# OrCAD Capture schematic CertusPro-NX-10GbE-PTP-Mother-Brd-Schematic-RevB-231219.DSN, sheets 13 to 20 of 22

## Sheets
13 12_FPGA_B5-2-1G_SFPS: size A3; title: 12_FPGA_B5-2-1G_SFPS
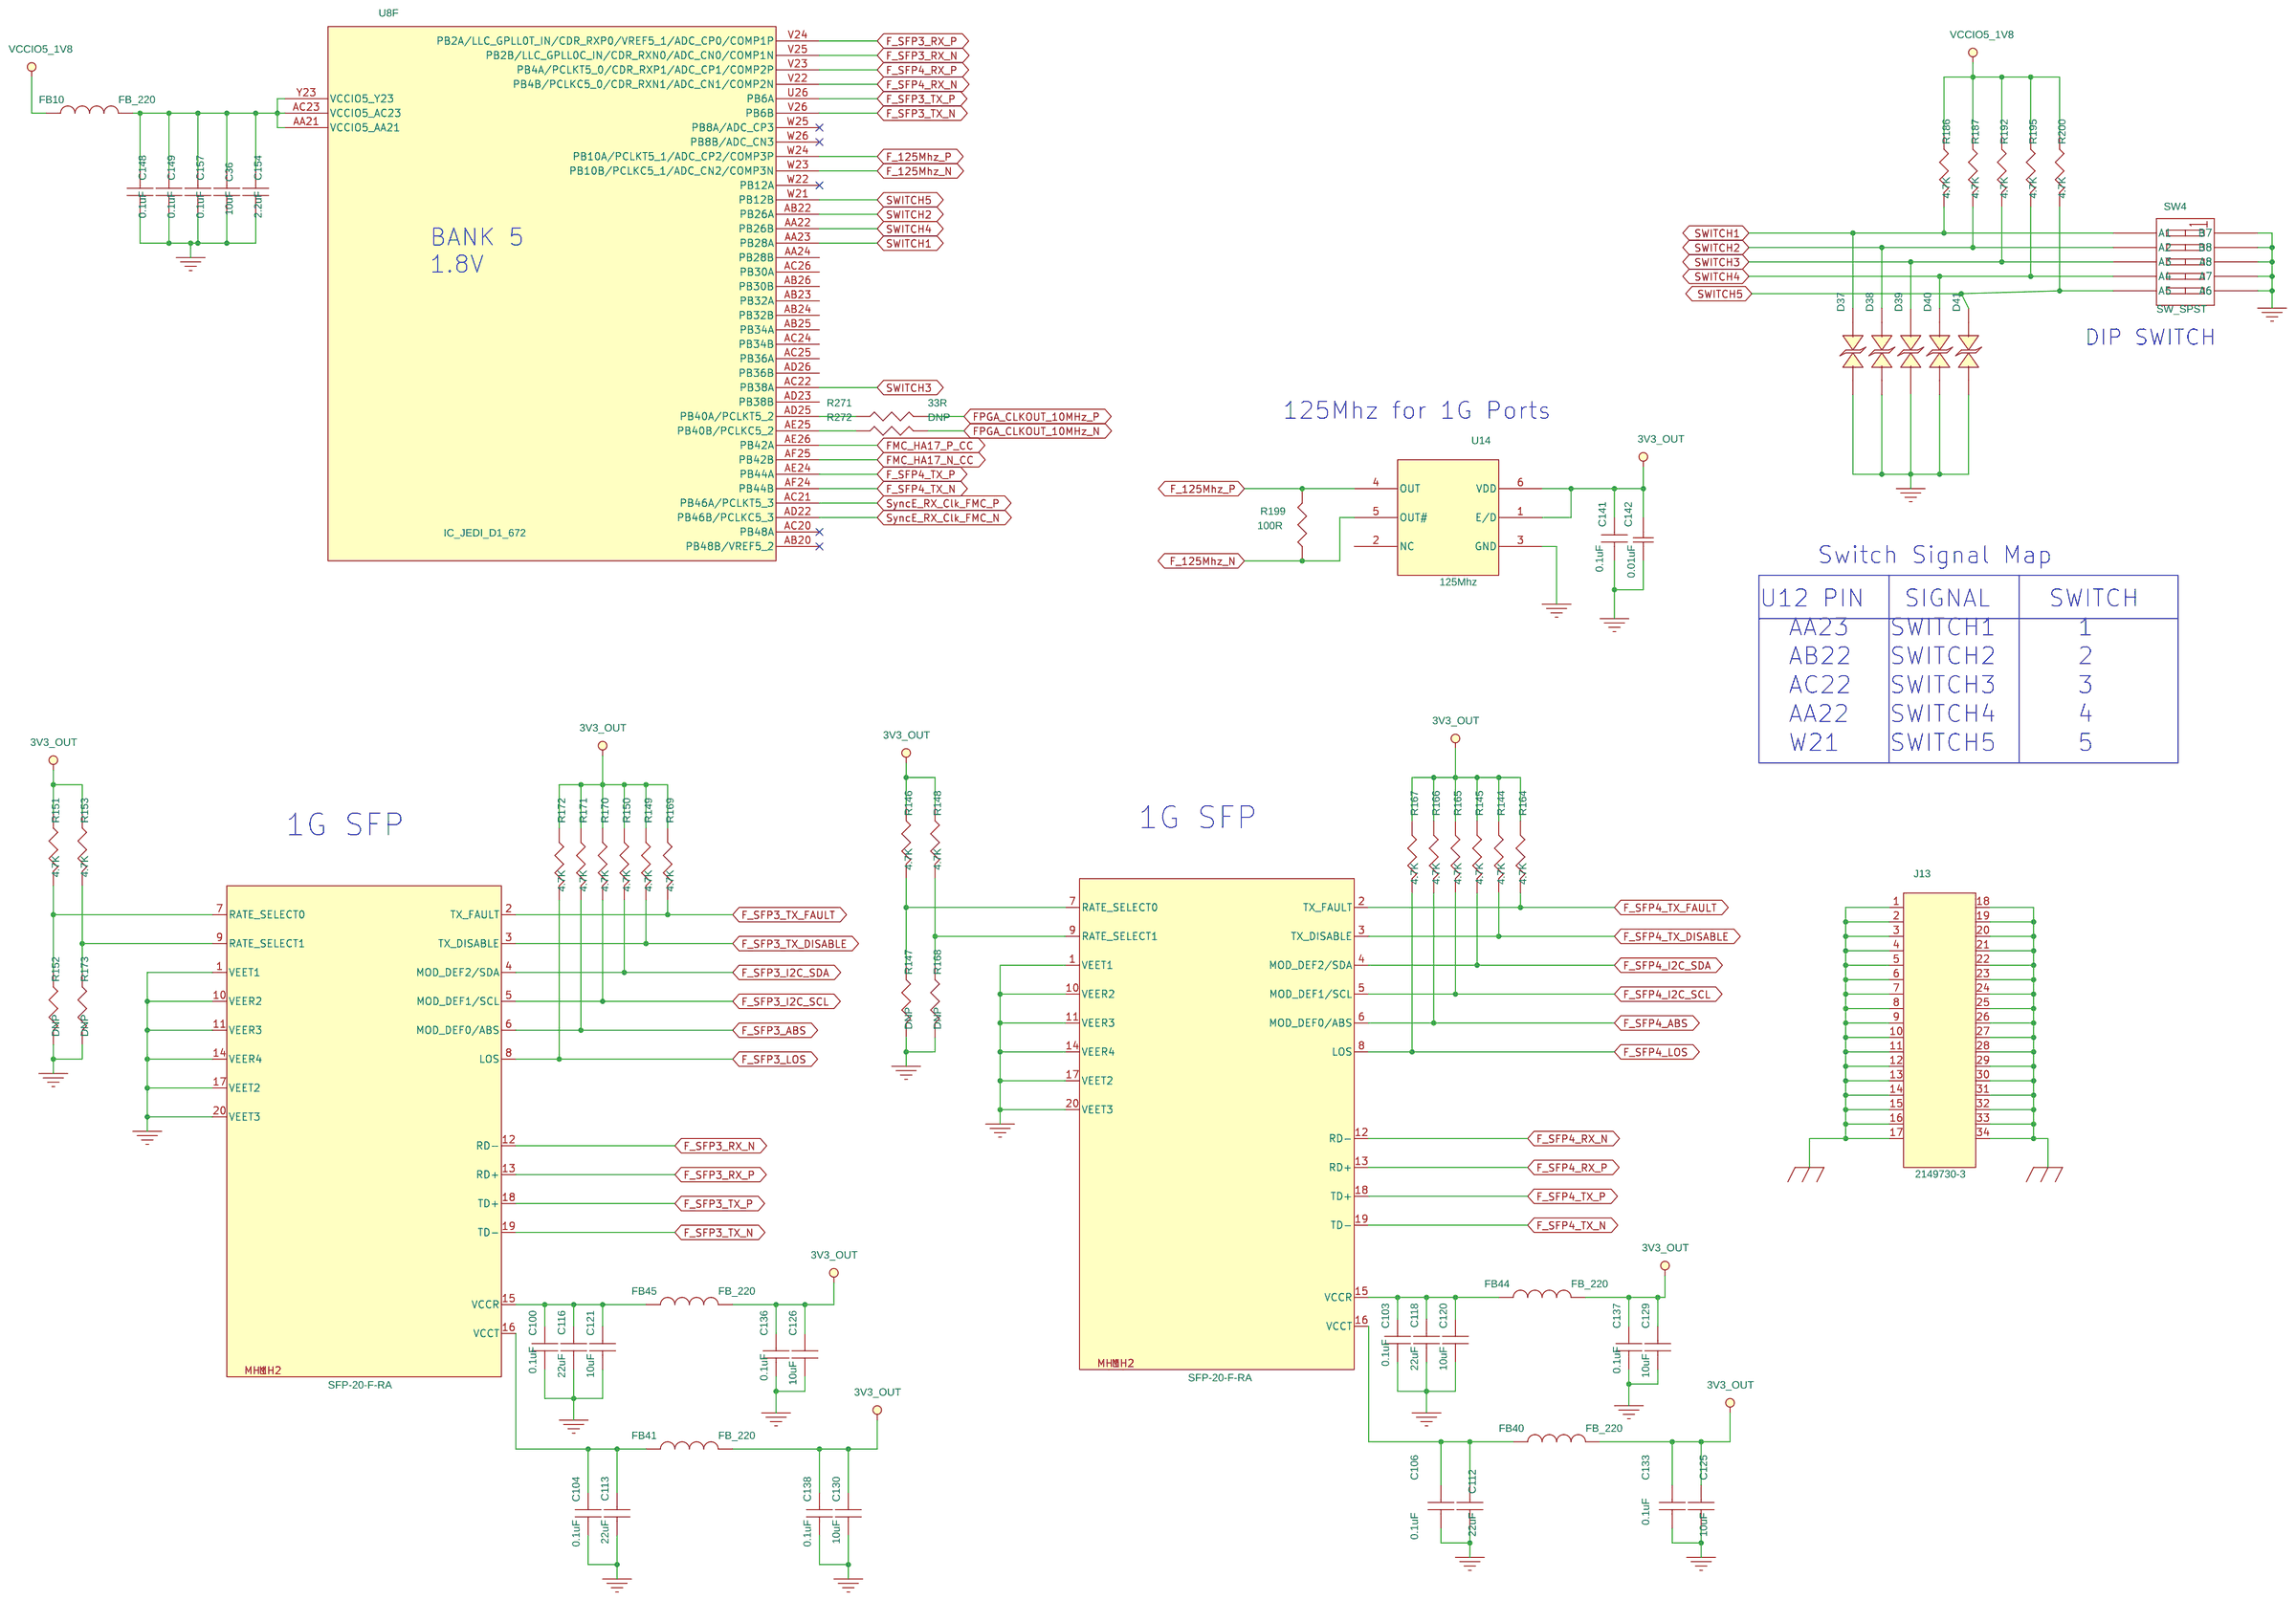
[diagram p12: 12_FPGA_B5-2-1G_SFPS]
14 10_FPGA_B2: size A3; title: 10_FPGA_B2-WR_Header
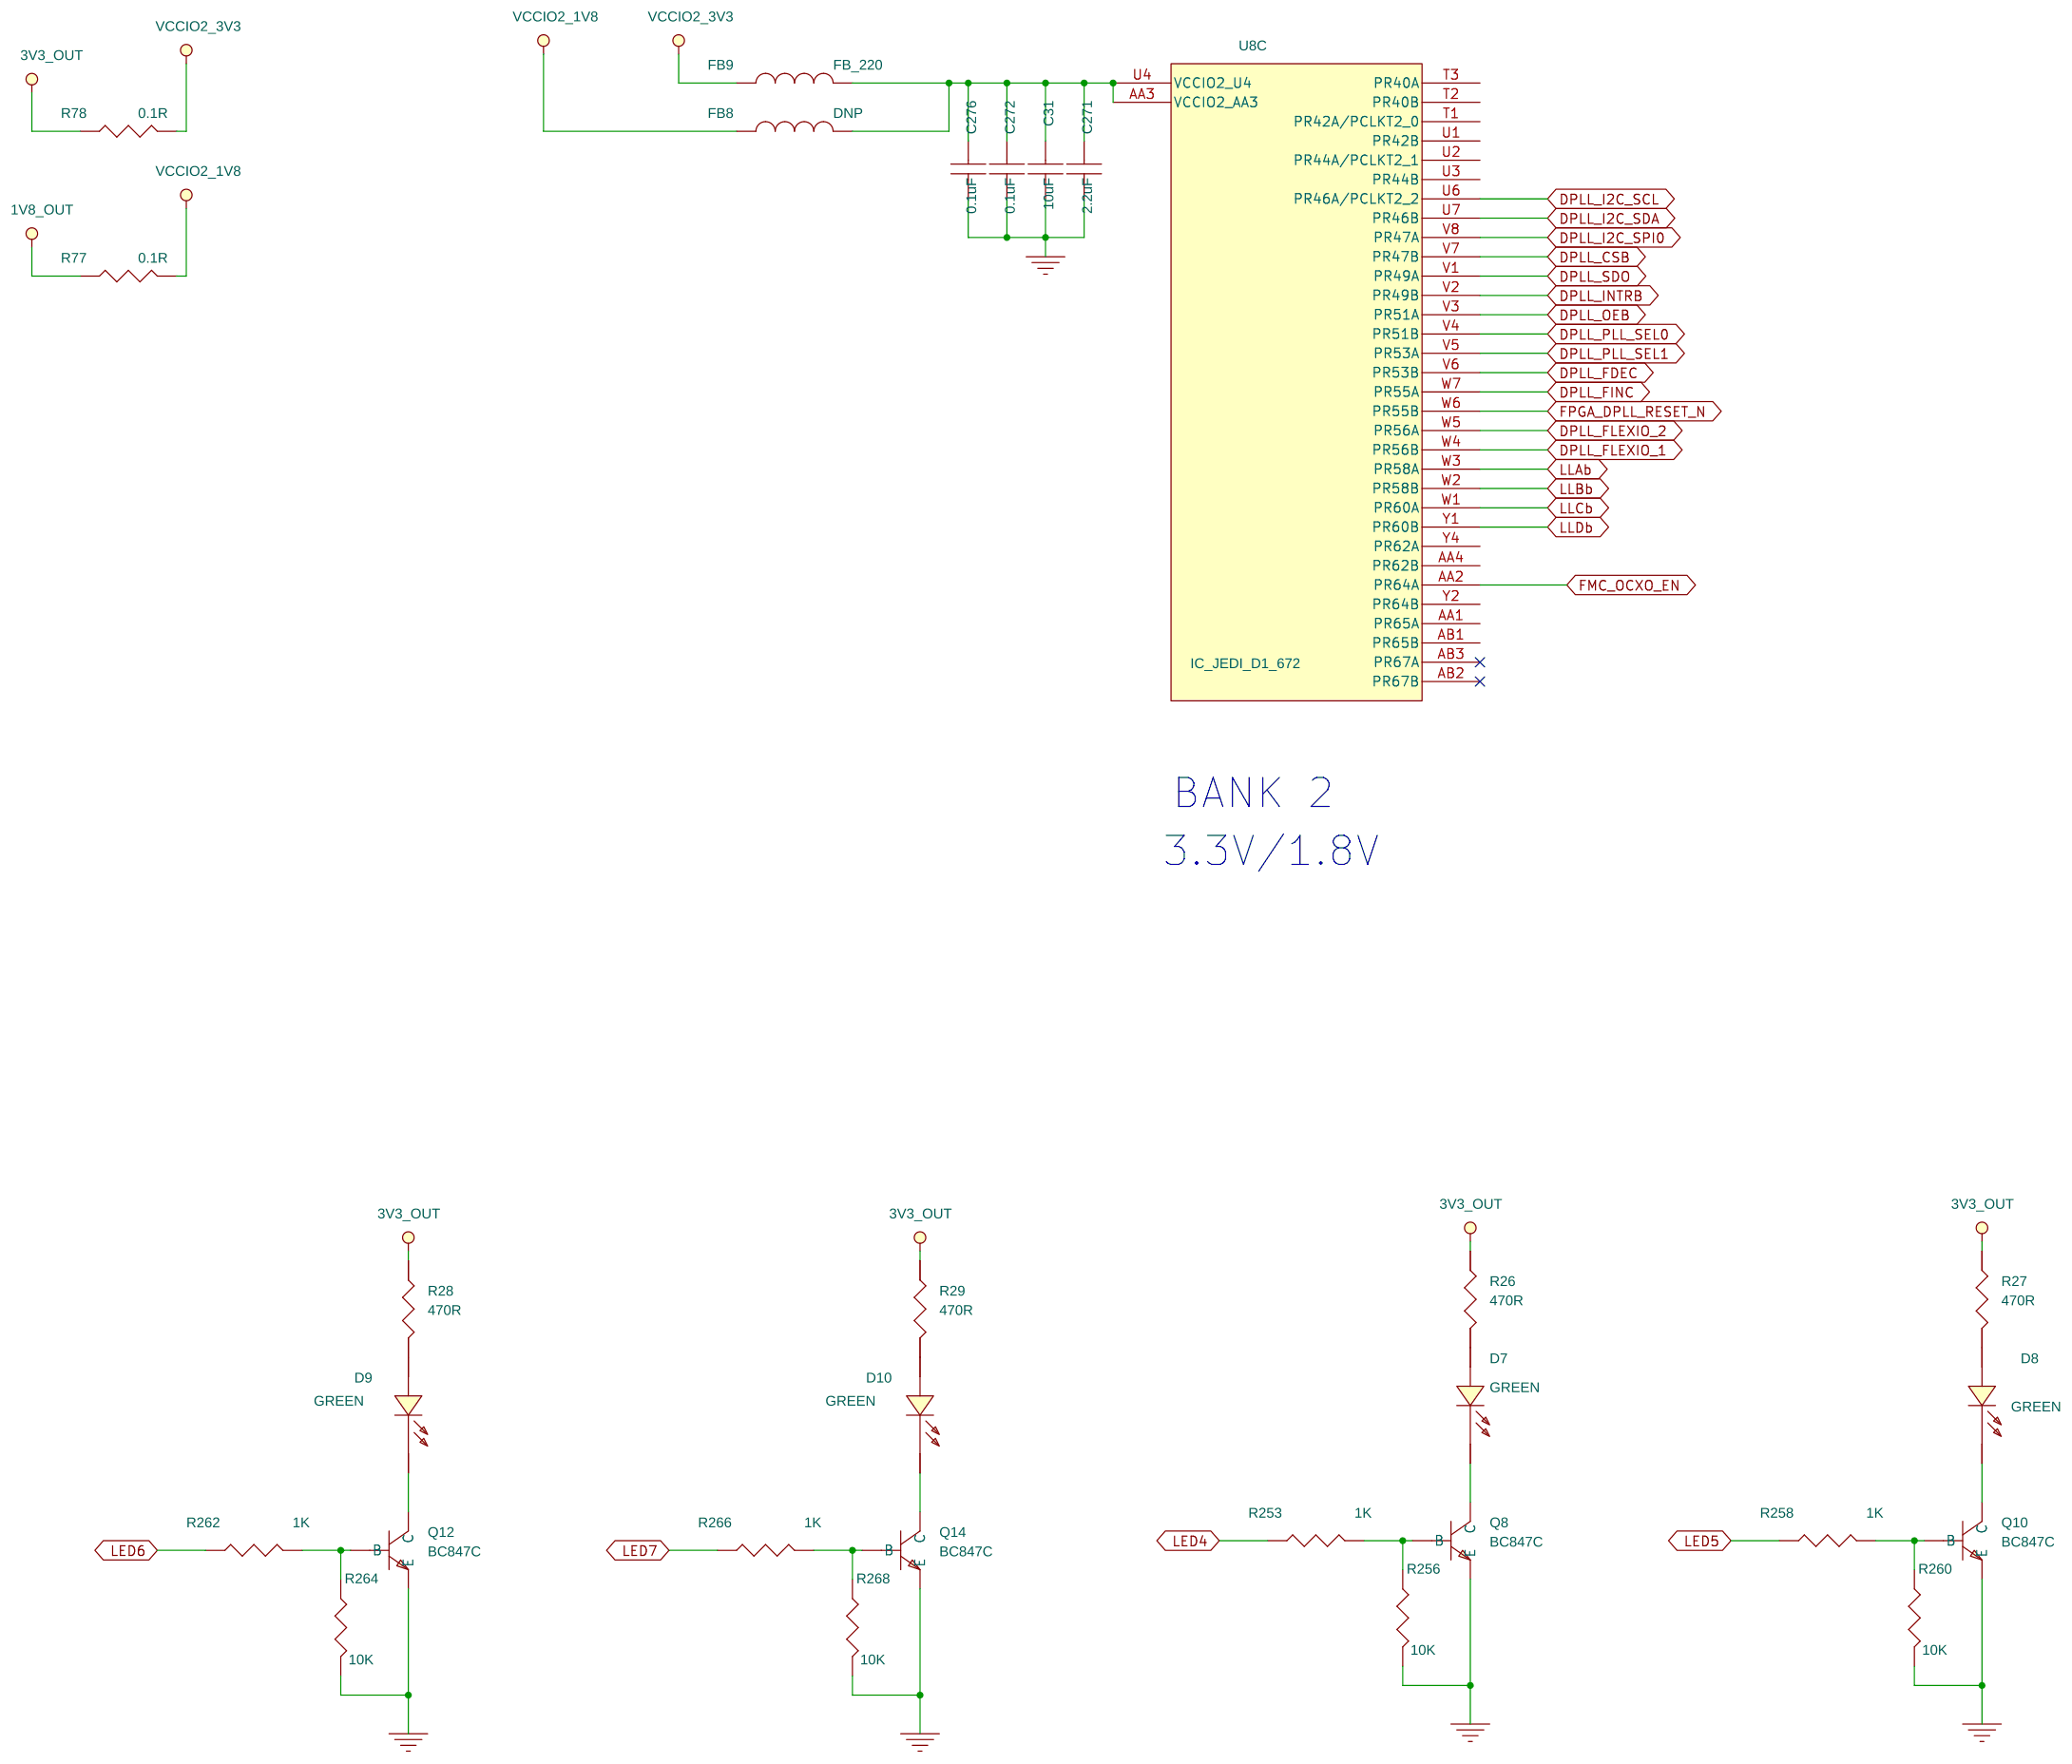
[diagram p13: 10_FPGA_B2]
15 15_FPGA_ADC: size A3; title: 15_FPGA_ADC
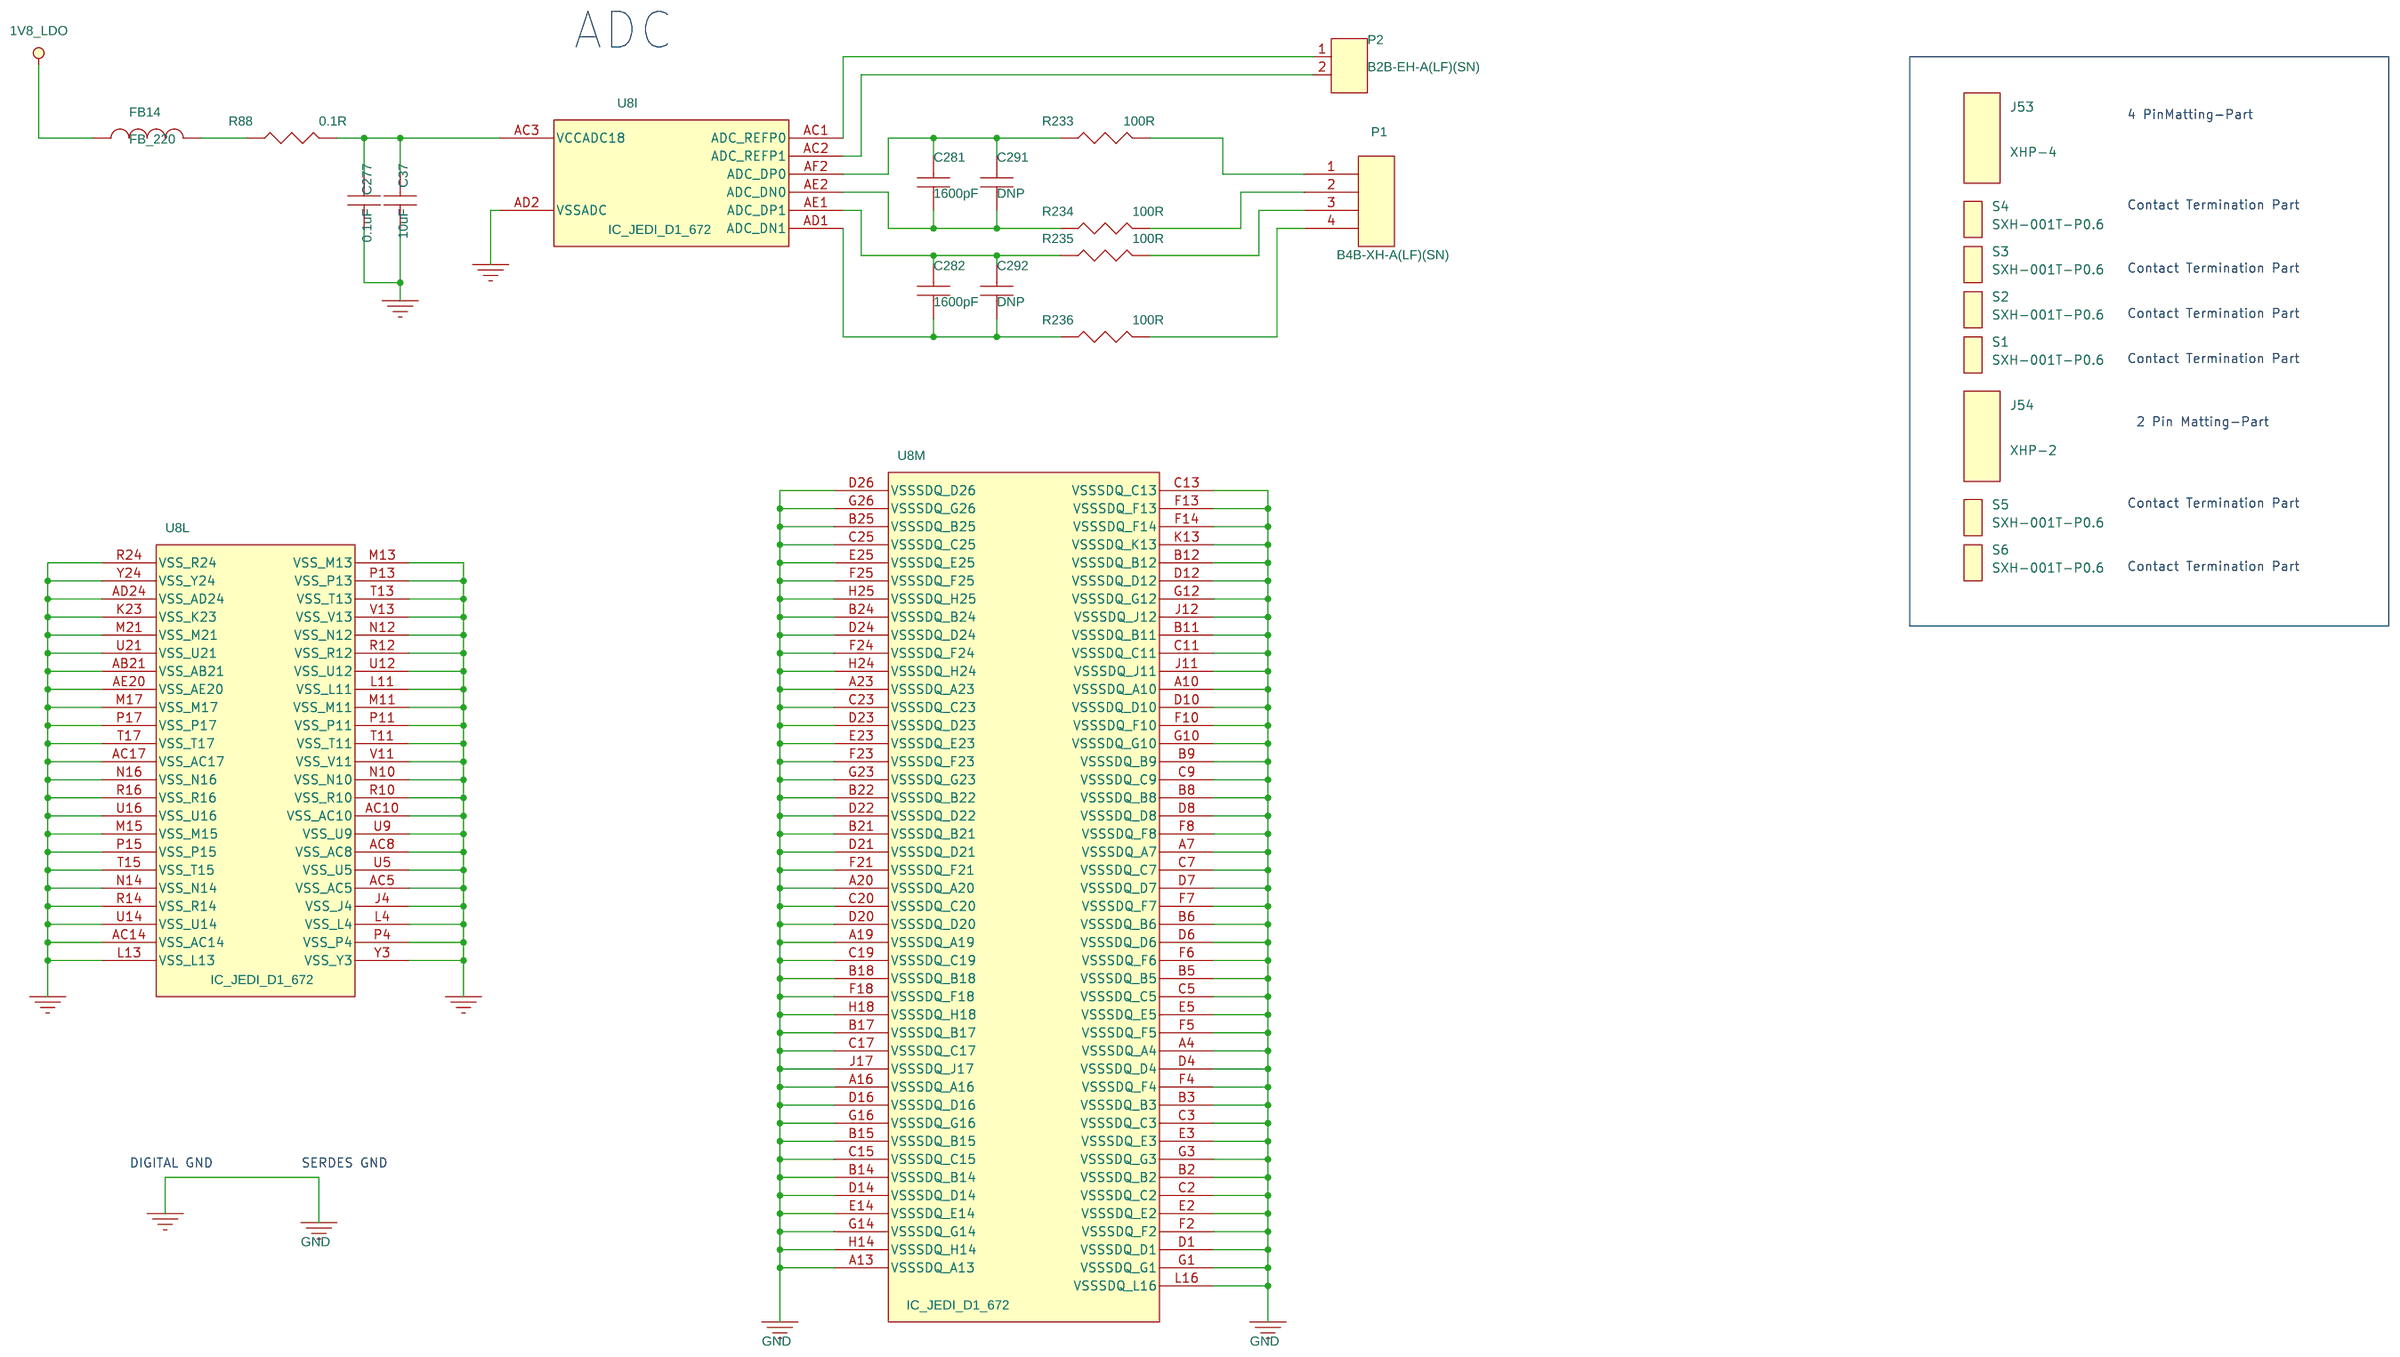
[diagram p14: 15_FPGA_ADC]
16 16_FTDI_USB: size A3; title: 16_FTDI_USB
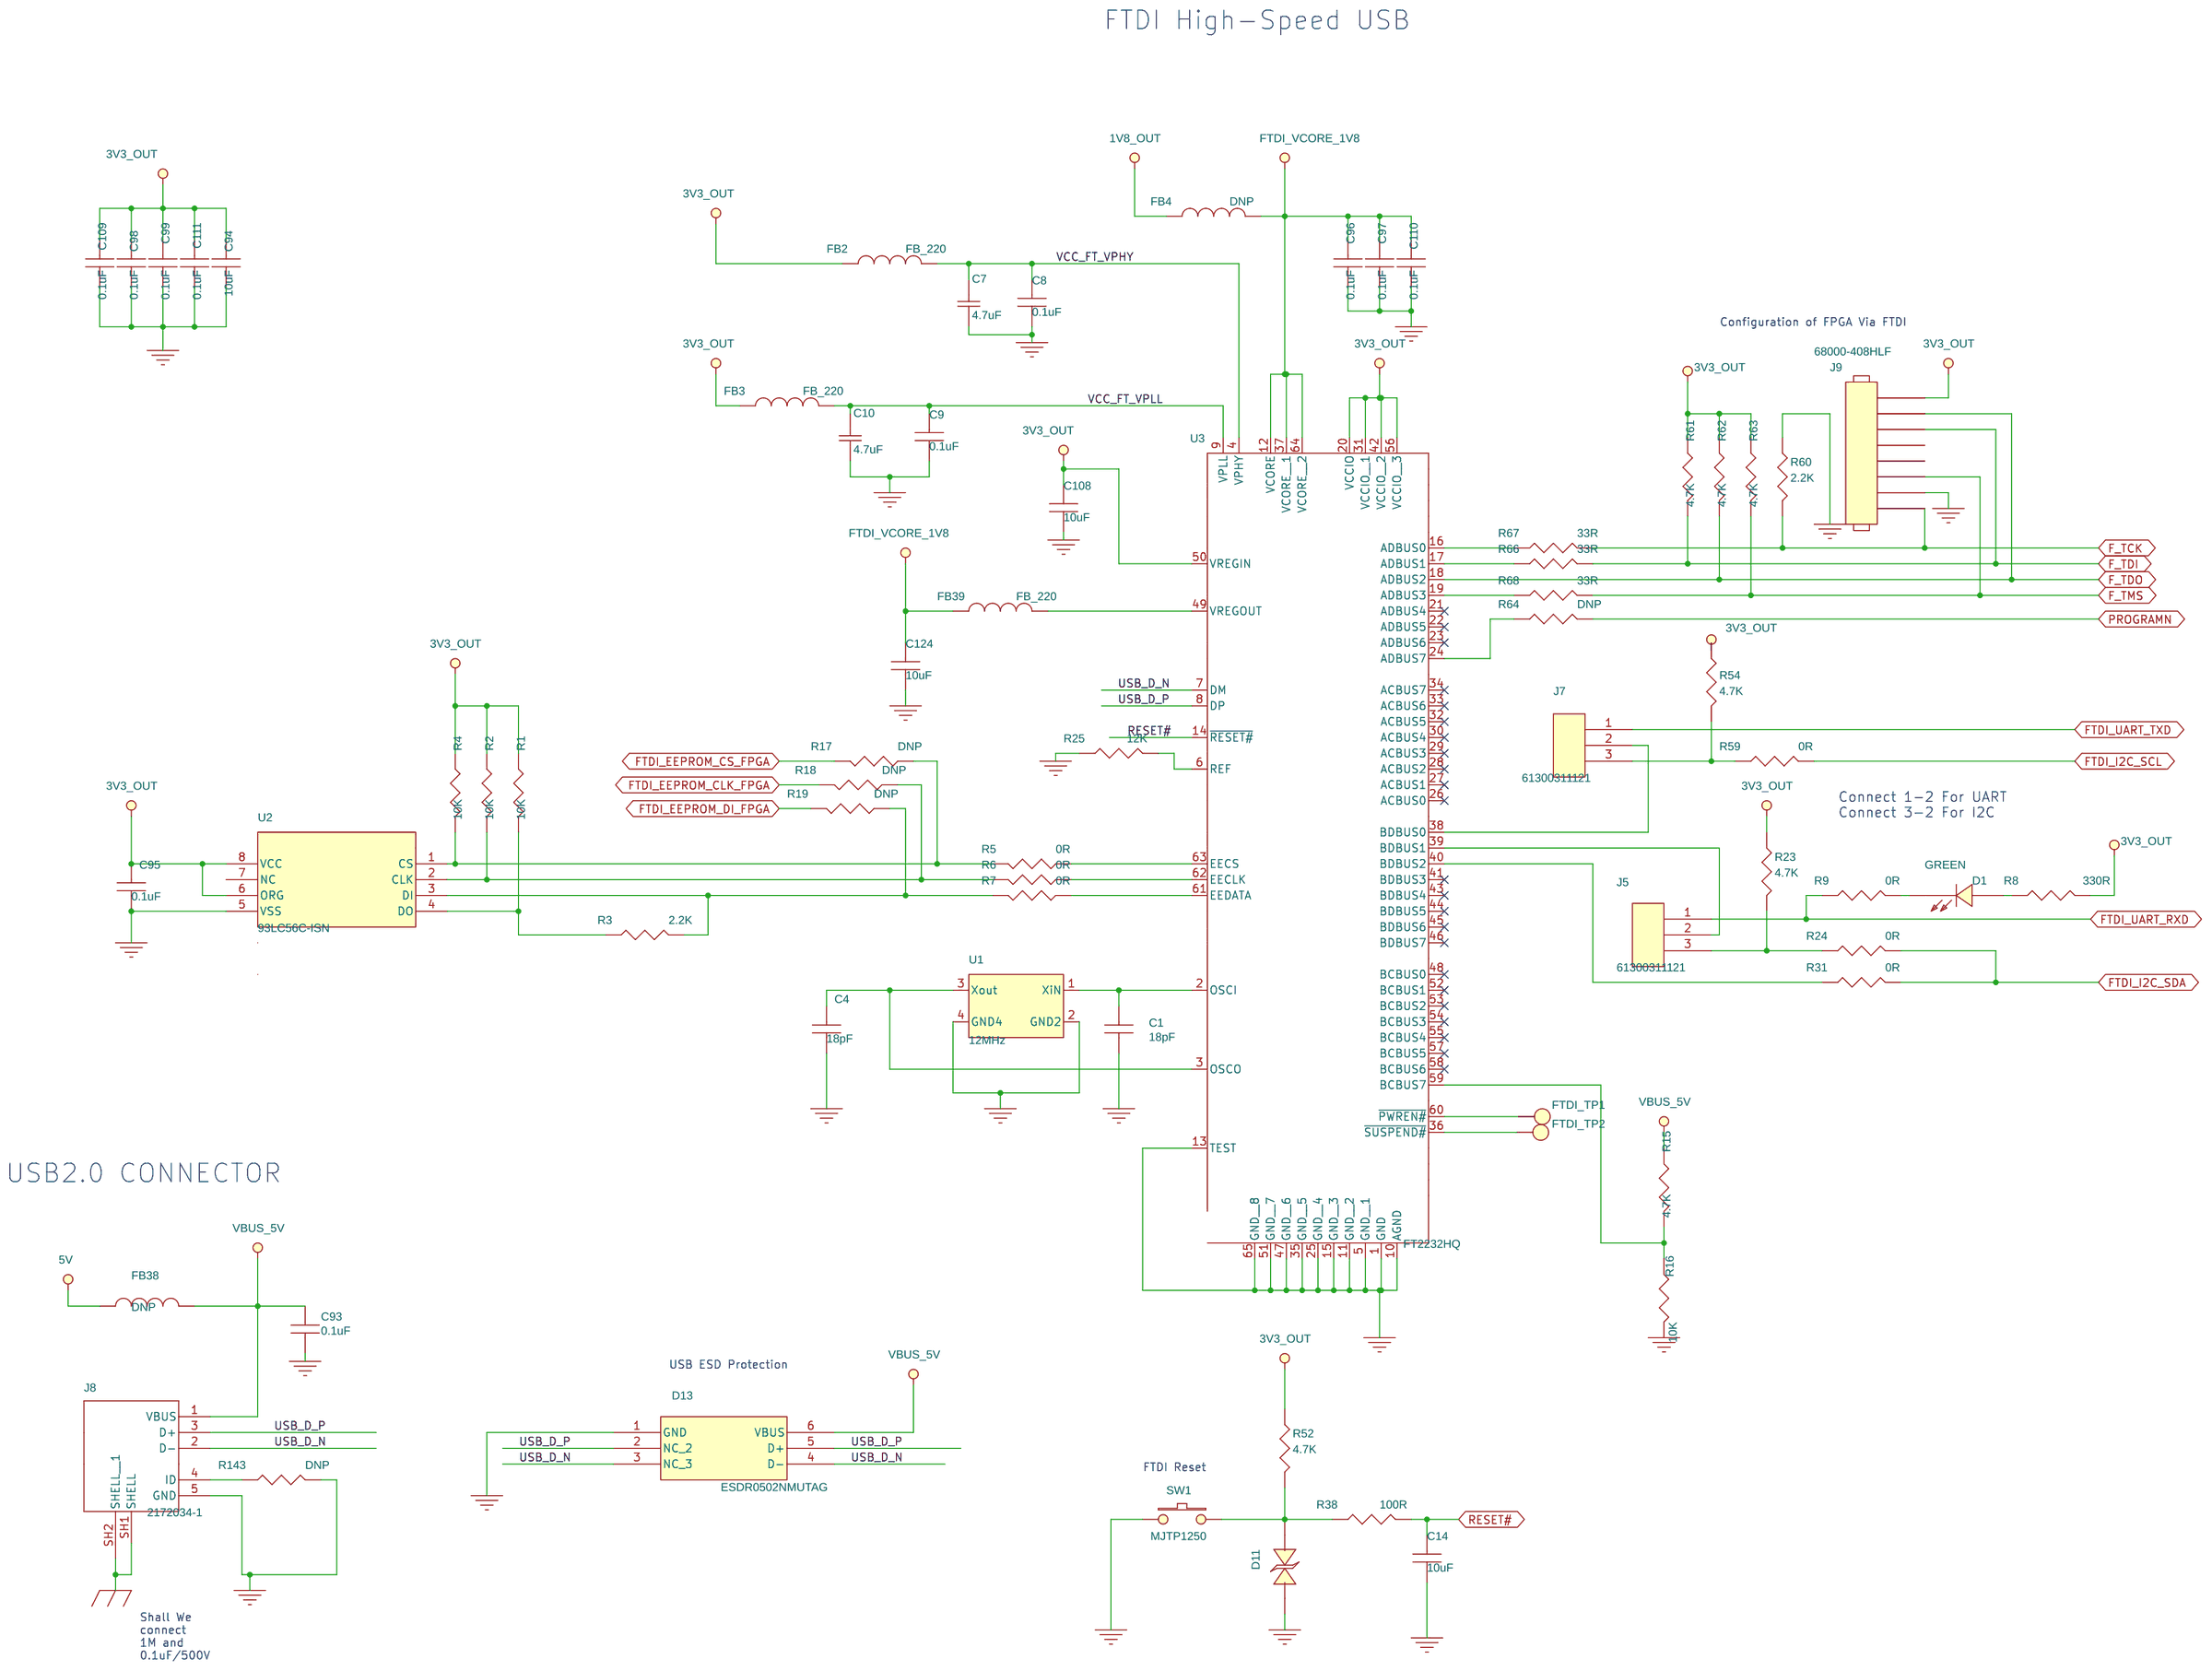
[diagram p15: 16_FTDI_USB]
17 06_FPGA_SerDes-PCIe: size A3; title: 06_FPGA_SerDes-PCIe
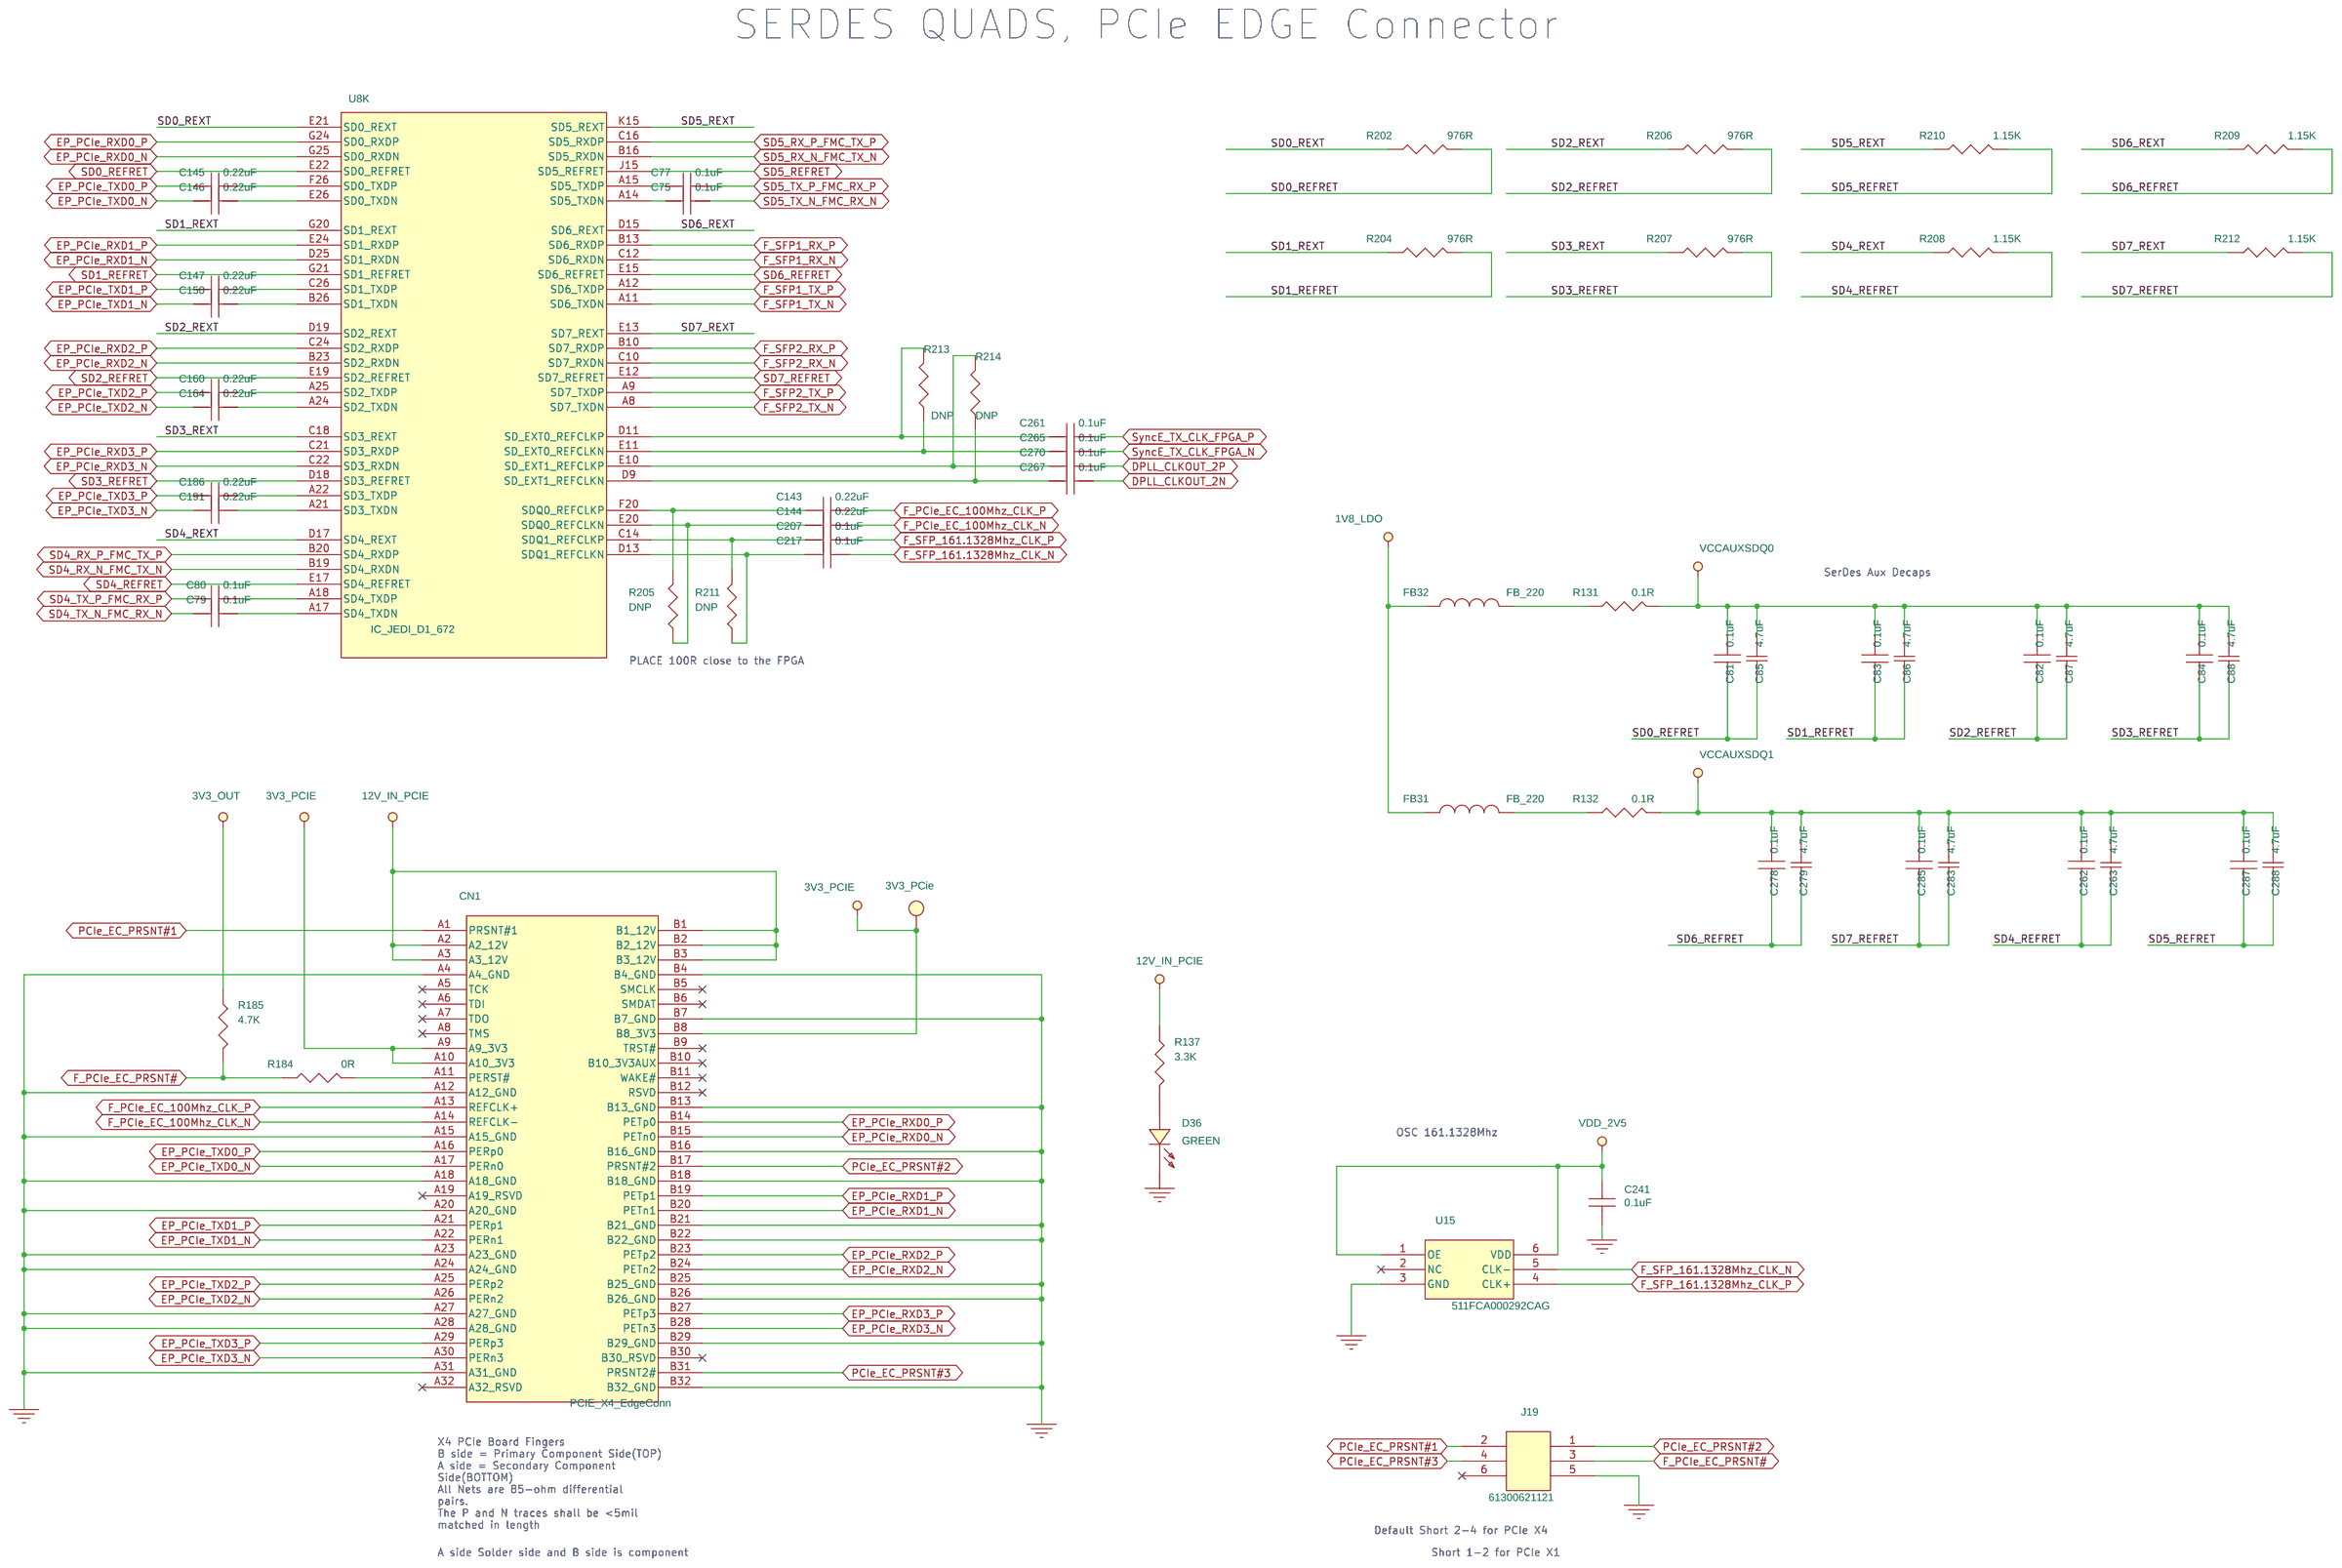
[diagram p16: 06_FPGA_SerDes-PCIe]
18 07_SerDes_PWR,2-10G SFPs: size A3; title: 07_SerDes_PWR,2-10G SFPs
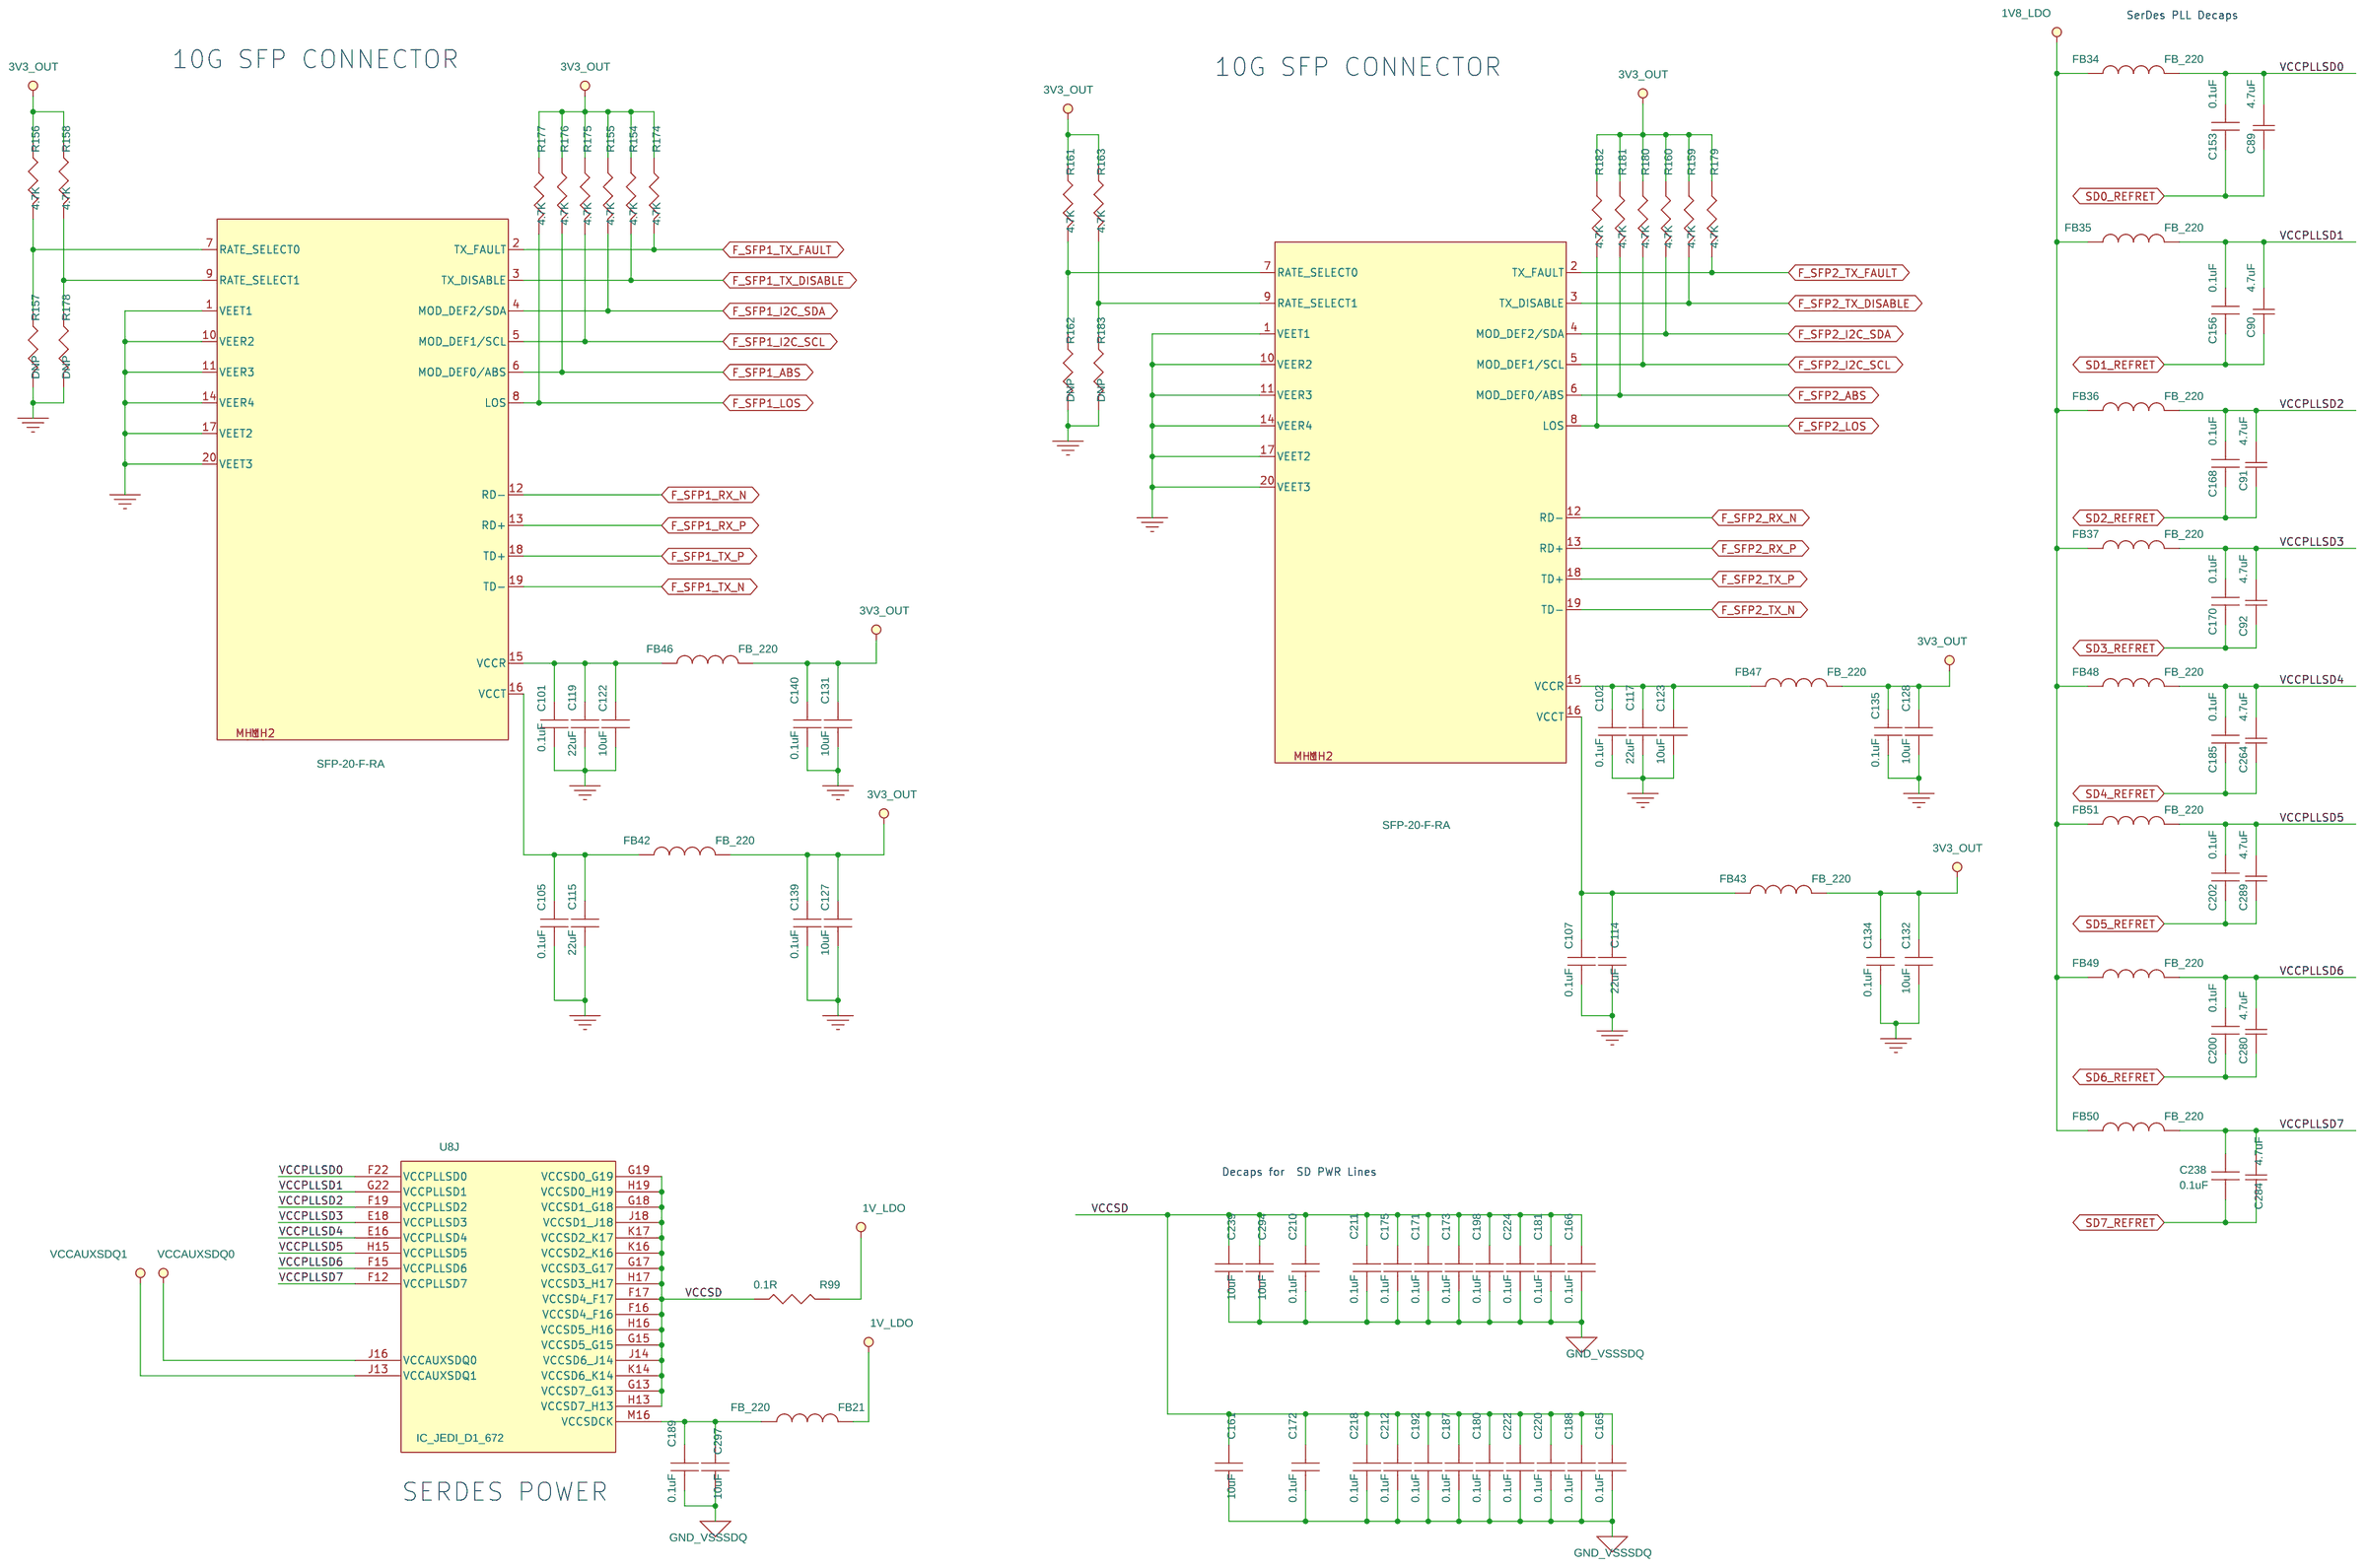
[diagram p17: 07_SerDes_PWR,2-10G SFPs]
19 14_FPGA_B7-GNSS_Ctrl: size A3; title: 14_FPGA_B7-
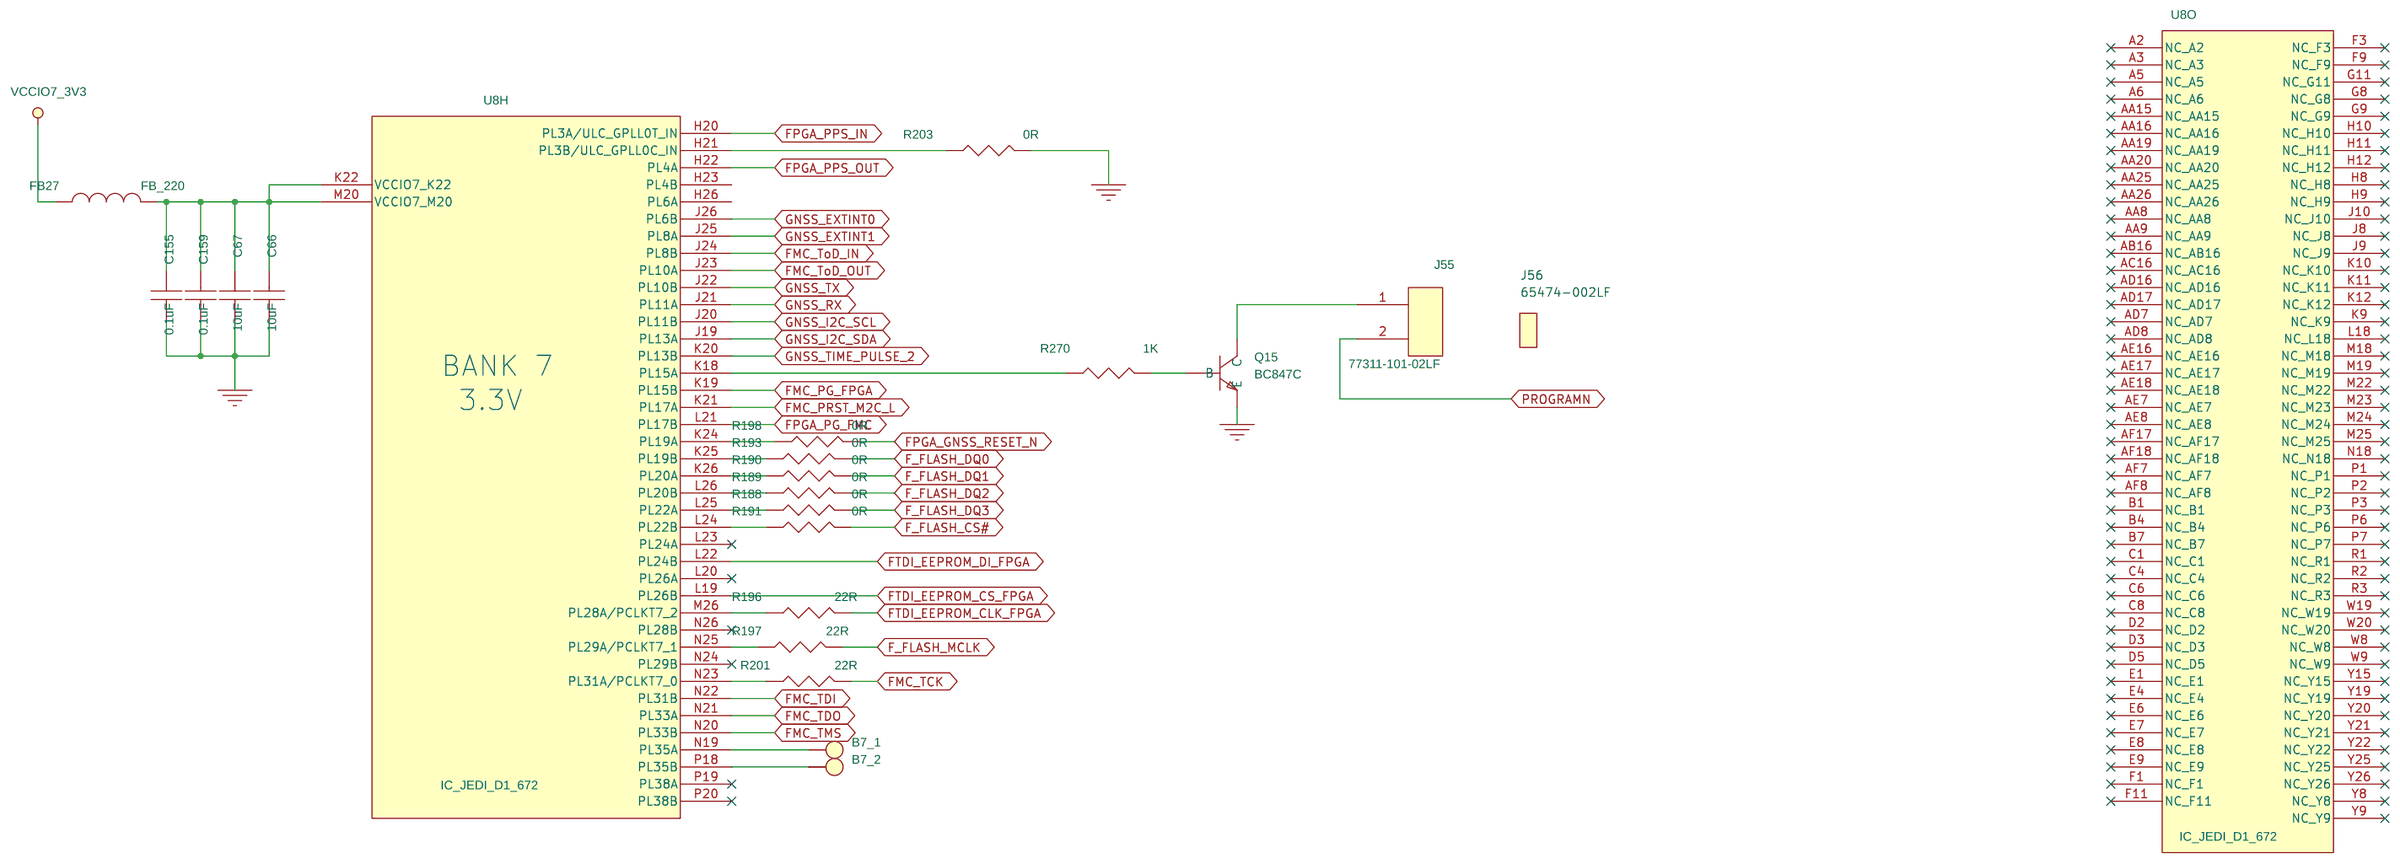
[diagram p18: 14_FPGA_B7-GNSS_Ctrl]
20 19_PS-5V,1V: size A3; title: 19_PS-5V,1V
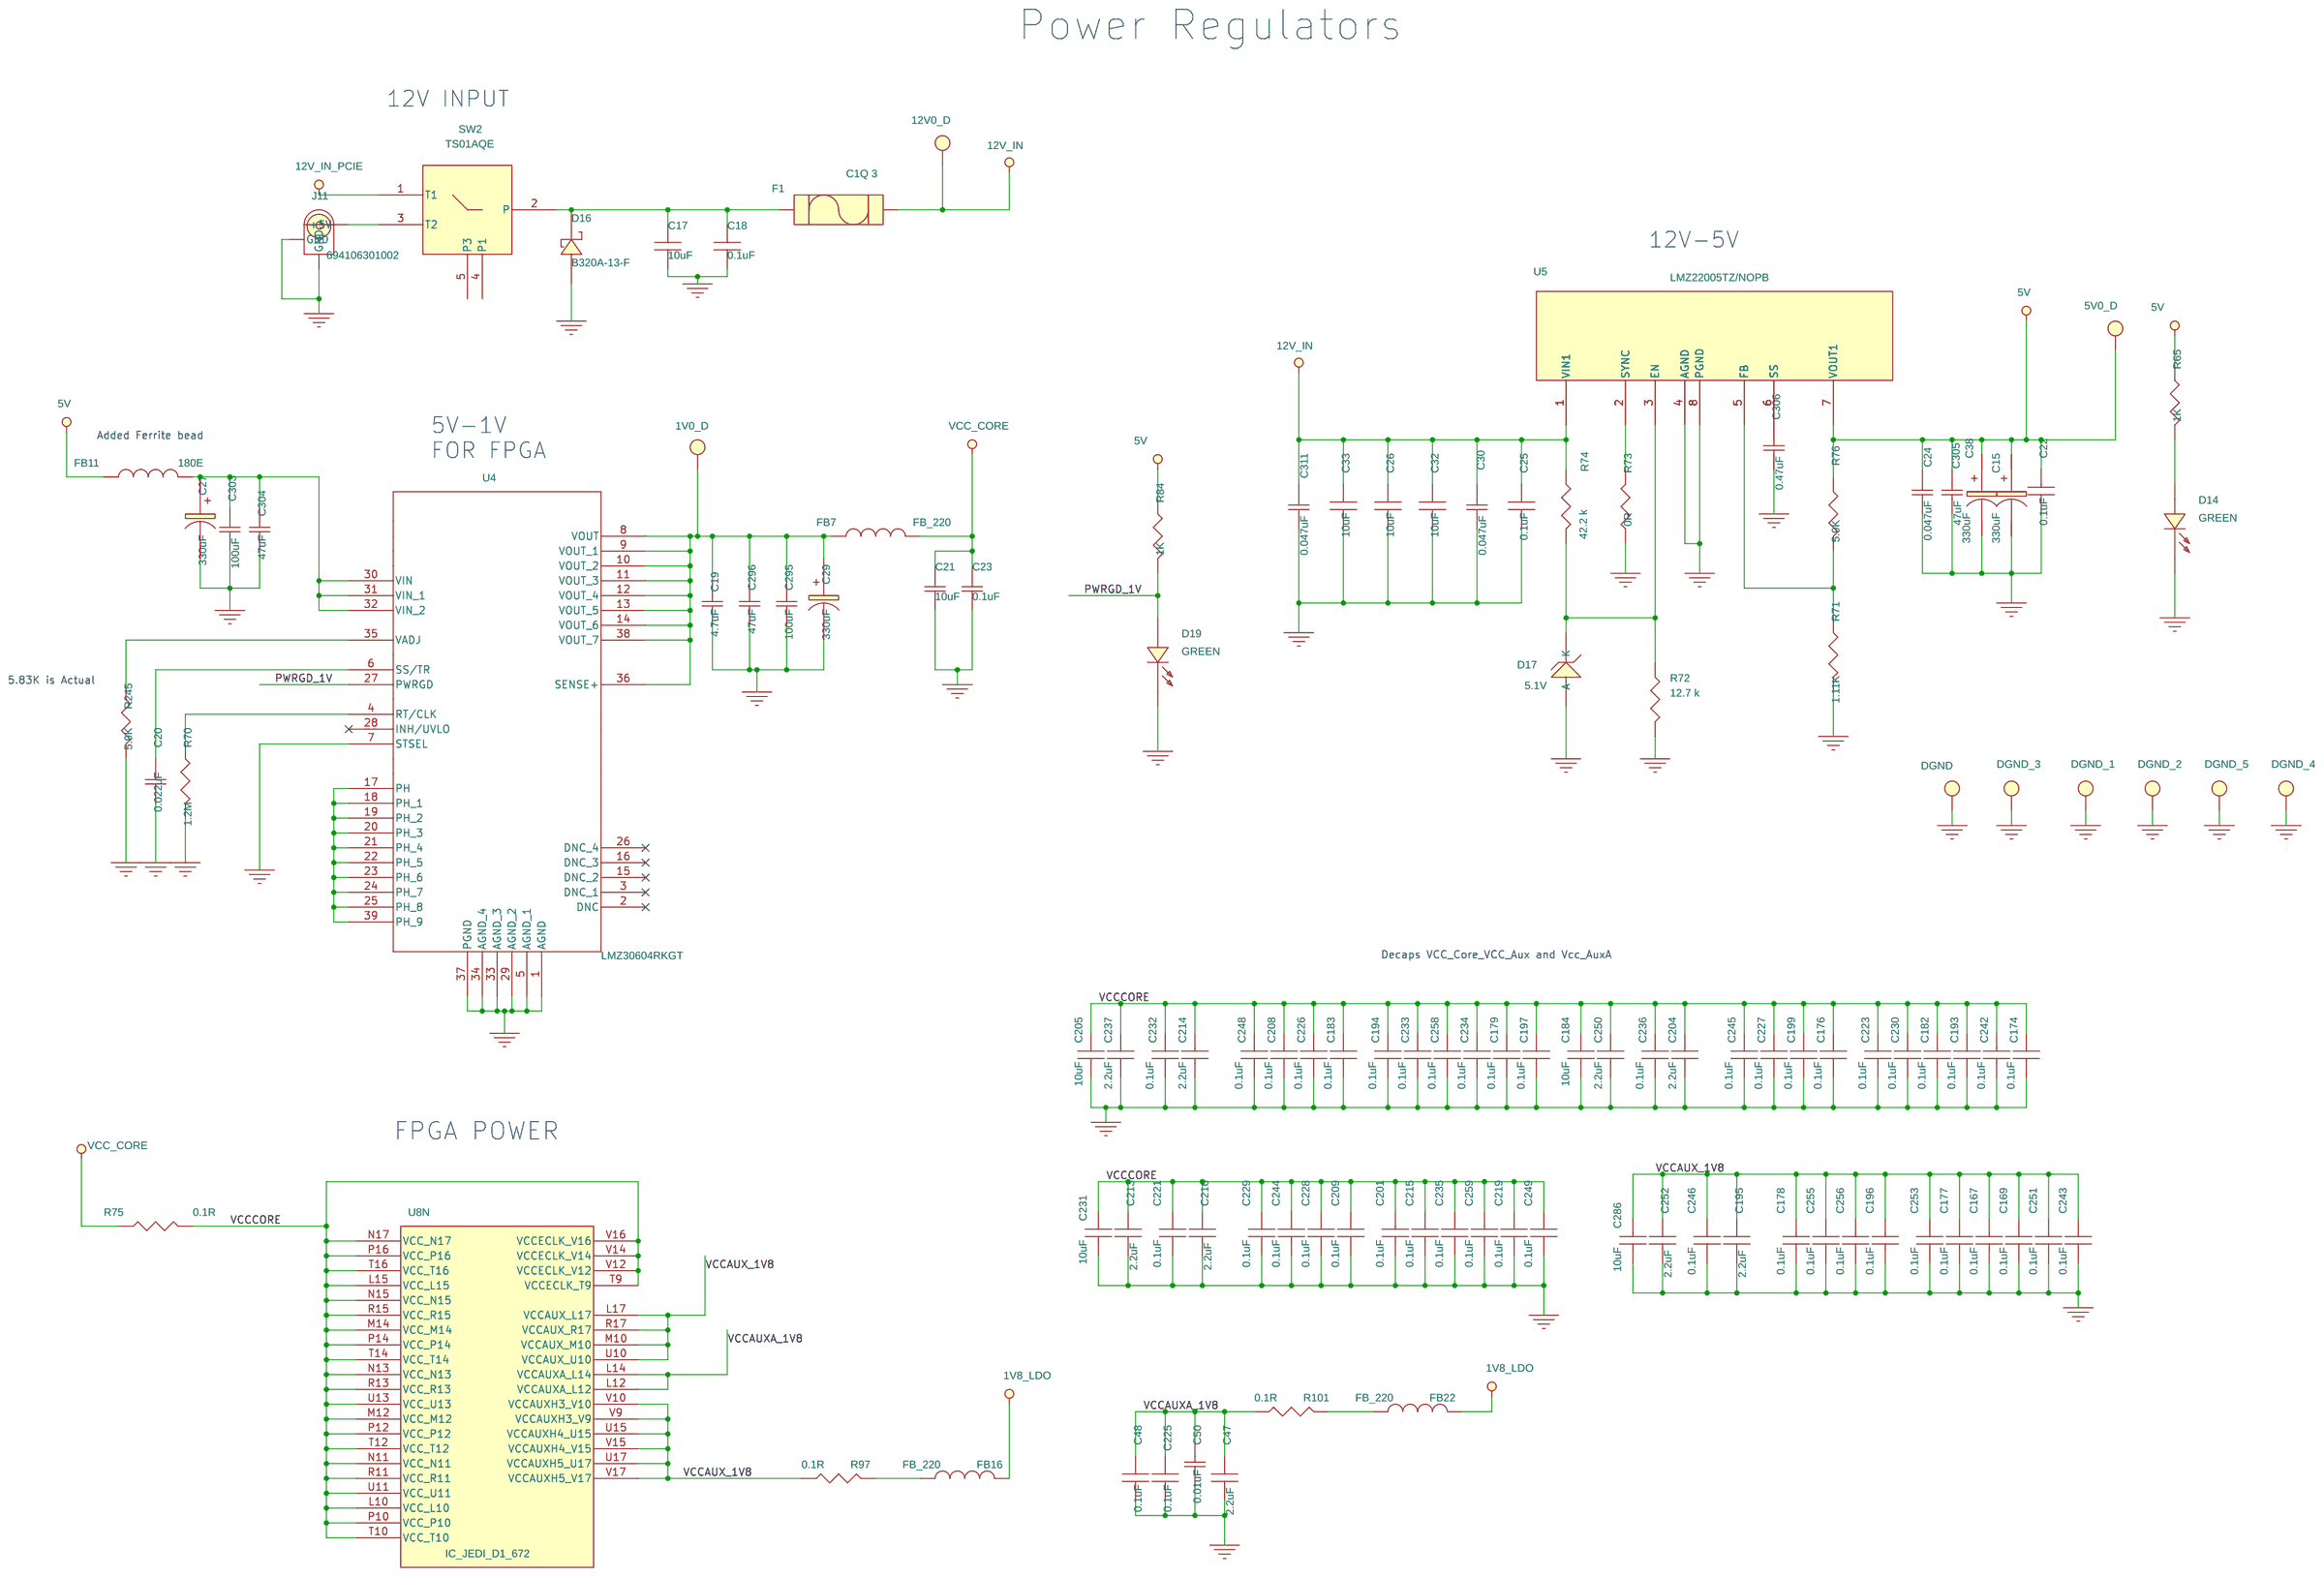
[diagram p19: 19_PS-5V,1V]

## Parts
sheet 06_FPGA_SerDes-PCIe
3V3_PCie  3V3_PCie  [TP_50]
C75  0.1uF  [cap0402]
C77  0.1uF  [cap0402]
C79  0.1uF  [cap0402]
C80  0.1uF  [cap0402]
C81  0.1uF  [cap0402]
C82  0.1uF  [cap0402]
C83  0.1uF  [cap0402]
C84  0.1uF  [cap0402]
C85  4.7uF  [cap0402]
C86  4.7uF  [cap0402]
C87  4.7uF  [cap0402]
C88  4.7uF  [cap0402]
C143  0.22uF  [cap0201]
C144  0.22uF  [cap0201]
C145  0.22uF  [cap0201]
C146  0.22uF  [cap0201]
C147  0.22uF  [cap0201]
C150  0.22uF  [cap0201]
C160  0.22uF  [cap0201]
C164  0.22uF  [cap0201]
C186  0.22uF  [cap0201]
C191  0.22uF  [cap0201]
C207  0.1uF  [cap0402]
C217  0.1uF  [cap0402]
C241  0.1uF  [cap0402]
C261  0.1uF  [cap0402]
C262  0.1uF  [cap0402]
C263  4.7uF  [cap0402]
C265  0.1uF  [cap0402]
C267  0.1uF  [cap0402]
C270  0.1uF  [cap0402]
C278  0.1uF  [cap0402]
C279  4.7uF  [cap0402]
C283  4.7uF  [cap0402]
C285  0.1uF  [cap0402]
C287  0.1uF  [cap0402]
C288  4.7uF  [cap0402]
CN1  PCIE_X4_EdgeConn  [pcie_64_pin]
D36  GREEN  [led_0603]
FB31  FB_220  [FB0603]
FB32  FB_220  [FB0603]
J19  61300621121  [conn_header_6pos]
R131  0.1R  [res0603]
R132  0.1R  [res0603]
R137  3.3K  [res0402]
R184  0R  [res0603]
R185  4.7K  [res0603]
R202  976R  [res0402]
R204  976R  [res0402]
R205  DNP  [res0201]
R206  976R  [res0402]
R207  976R  [res0402]
R208  1.15K  [res0402]
R209  1.15K  [res0402]
R210  1.15K  [res0402]
R211  DNP  [res0201]
R212  1.15K  [res0402]
R213  DNP  [res0201]
R214  DNP  [res0201]
U15  511FCA000292CAG  [osc_32x25_6pin_1p25mm]
sheet 07_SerDes_PWR,2-10G SFPs
C89  4.7uF  [cap0402]
C90  4.7uF  [cap0402]
C91  4.7uF  [cap0402]
C92  4.7uF  [cap0402]
C101  0.1uF  [cap0402]
C102  0.1uF  [cap0402]
C105  0.1uF  [cap0402]
C107  0.1uF  [cap0402]
C114  22uF  [cap0805]
C115  22uF  [cap0805]
C117  22uF  [cap0805]
C119  22uF  [cap0805]
C122  10uF  [cap1206]
C123  10uF  [cap1206]
C127  10uF  [cap1206]
C128  10uF  [cap1206]
C131  10uF  [cap1206]
C132  10uF  [cap1206]
C134  0.1uF  [cap0402]
C135  0.1uF  [cap0402]
C139  0.1uF  [cap0402]
C140  0.1uF  [cap0402]
C153  0.1uF  [cap0402]
C156  0.1uF  [cap0402]
C161  10uF  [cap0603]
C165  0.1uF  [cap0402]
C166  0.1uF  [cap0402]
C168  0.1uF  [cap0402]
C170  0.1uF  [cap0402]
C171  0.1uF  [cap0402]
C172  0.1uF  [cap0402]
C173  0.1uF  [cap0402]
C175  0.1uF  [cap0402]
C180  0.1uF  [cap0402]
C181  0.1uF  [cap0402]
C185  0.1uF  [cap0402]
C187  0.1uF  [cap0402]
C188  0.1uF  [cap0402]
C189  0.1uF  [cap0402]
C192  0.1uF  [cap0402]
C198  0.1uF  [cap0402]
C200  0.1uF  [cap0402]
C202  0.1uF  [cap0402]
C210  0.1uF  [cap0402]
C211  0.1uF  [cap0402]
C212  0.1uF  [cap0402]
C218  0.1uF  [cap0402]
C220  0.1uF  [cap0402]
C222  0.1uF  [cap0402]
C224  0.1uF  [cap0402]
C238  0.1uF  [cap0402]
C239  10uF  [cap0603]
C264  4.7uF  [cap0402]
C280  4.7uF  [cap0402]
C284  4.7uF  [cap0402]
C289  4.7uF  [cap0402]
C294  10uF  [cap0603]
C297  10uF  [cap0603]
FB21  FB_220  [FB0603]
FB34  FB_220  [FB0603]
FB35  FB_220  [FB0603]
FB36  FB_220  [FB0603]
FB37  FB_220  [FB0603]
FB42  FB_220  [FB0603]
FB43  FB_220  [FB0603]
FB46  FB_220  [FB0603]
FB47  FB_220  [FB0603]
FB48  FB_220  [FB0603]
FB49  FB_220  [FB0603]
FB50  FB_220  [FB0603]
FB51  FB_220  [FB0603]
J16  SFP-20-F-RA  [SFP_1888247-1_CONN_SMD]
J17  SFP-20-F-RA  [SFP_1888247-1_CONN_SMD]
R99  0.1R  [res0603]
R154  4.7K  [res0603]
R155  4.7K  [res0603]
R156  4.7K  [res0603]
R157  DNP  [res0603]
R158  4.7K  [res0603]
R159  4.7K  [res0603]
R160  4.7K  [res0603]
R161  4.7K  [res0603]
R162  DNP  [res0603]
R163  4.7K  [res0603]
R174  4.7K  [res0603]
R175  4.7K  [res0603]
R176  4.7K  [res0603]
R177  4.7K  [res0603]
R178  DNP  [res0603]
R179  4.7K  [res0603]
R180  4.7K  [res0603]
R181  4.7K  [res0603]
R182  4.7K  [res0603]
R183  DNP  [res0603]
sheet 10_FPGA_B2
C31  10uF  [cap0603]
C271  2.2uF  [cap0402]
C272  0.1uF  [cap0402]
C276  0.1uF  [cap0402]
D7  GREEN  [led_0603]
D8  GREEN  [led_0603]
D9  GREEN  [led_0603]
D10  GREEN  [led_0603]
FB8  DNP  [FB0603]
FB9  FB_220  [FB0603]
Q8  BC847C  [sot23_3]
Q10  BC847C  [sot23_3]
Q12  BC847C  [sot23_3]
Q14  BC847C  [sot23_3]
R26  470R  [res0402]
R27  470R  [res0402]
R28  470R  [res0402]
R29  470R  [res0402]
R77  0.1R  [res0603]
R78  0.1R  [res0603]
R253  1K  [res0603]
R256  10K  [res0402]
R258  1K  [res0603]
R260  10K  [res0402]
R262  1K  [res0603]
R264  10K  [res0402]
R266  1K  [res0603]
R268  10K  [res0402]
sheet 12_FPGA_B5-2-1G_SFPS
C36  10uF  [cap0603]
C100  0.1uF  [cap0402]
C103  0.1uF  [cap0402]
C104  0.1uF  [cap0402]
C106  0.1uF  [cap0402]
C112  22uF  [cap0805]
C113  22uF  [cap0805]
C116  22uF  [cap0805]
C118  22uF  [cap0805]
C120  10uF  [cap1206]
C121  10uF  [cap1206]
C125  10uF  [cap1206]
C126  10uF  [cap1206]
C129  10uF  [cap1206]
C130  10uF  [cap1206]
C133  0.1uF  [cap0402]
C136  0.1uF  [cap0402]
C137  0.1uF  [cap0402]
C138  0.1uF  [cap0402]
C141  0.1uF  [cap0402]
C142  0.01uF  [cap0603]
C148  0.1uF  [cap0402]
C149  0.1uF  [cap0402]
C154  2.2uF  [cap0402]
C157  0.1uF  [cap0402]
D37  DIODE_SUPPRESSOR ESD 30VDC 0402  [ESD0402]
D38  DIODE_SUPPRESSOR ESD 30VDC 0402  [ESD0402]
D39  DIODE_SUPPRESSOR ESD 30VDC 0402  [ESD0402]
D40  DIODE_SUPPRESSOR ESD 30VDC 0402  [ESD0402]
D41  DIODE_SUPPRESSOR ESD 30VDC 0402  [ESD0402]
FB10  FB_220  [FB0603]
FB40  FB_220  [FB0603]
FB41  FB_220  [FB0603]
FB44  FB_220  [FB0603]
FB45  FB_220  [FB0603]
J10  SFP-20-F-RA  [SFP_1888247-1_CONN_SMD]
J12  SFP-20-F-RA  [SFP_1888247-1_CONN_SMD]
J13  2149730-3  [SFP_2149730-3]
R144  4.7K  [res0603]
R145  4.7K  [res0603]
R146  4.7K  [res0603]
R147  DNP  [res0603]
R148  4.7K  [res0603]
R149  4.7K  [res0603]
R150  4.7K  [res0603]
R151  4.7K  [res0603]
R152  DNP  [res0603]
R153  4.7K  [res0603]
R164  4.7K  [res0603]
R165  4.7K  [res0603]
R166  4.7K  [res0603]
R167  4.7K  [res0603]
R168  DNP  [res0603]
R169  4.7K  [res0603]
R170  4.7K  [res0603]
R171  4.7K  [res0603]
R172  4.7K  [res0603]
R173  DNP  [res0603]
R186  4.7K  [res0603]
R187  4.7K  [res0603]
R192  4.7K  [res0603]
R195  4.7K  [res0603]
R199  100R  [res0402]
R200  4.7K  [res0603]
R271  33R  [res0402]
R272  DNP  [res0402]
SW4  SW_SPST  [sw_spst-05_smd]
U14  125Mhz  [6-smdx]
sheet 14_FPGA_B7-GNSS_Ctrl
B7_1  1V8P  [TP_50]
B7_2  1V8P  [TP_50]
C66  10uF  [cap0603]
C67  10uF  [cap0603]
C155  0.1uF  [cap0402]
C159  0.1uF  [cap0402]
FB27  FB_220  [FB0603]
J55  77311-101-02LF  [HDR_1X2]
J56  65474-002LF  [NA]
Q15  BC847C  [sot23_3]
R188  0R  [res0402]
R189  0R  [res0402]
R190  0R  [res0402]
R191  0R  [res0402]
R193  0R  [res0402]
R196  22R  [res0402]
R197  22R  [res0402]
R198  0R  [res0402]
R201  22R  [res0402]
R203  0R  [res0402]
R270  1K  [res0402]
sheet 15_FPGA_ADC
C37  10uF  [cap0603]
C277  0.1uF  [cap0402]
C281  1600pF  [cap0402]
C282  1600pF  [cap0402]
C291  DNP  [cap0402]
C292  DNP  [cap0402]
FB14  FB_220  [FB0603]
J53  XHP-4  [NA]
J54  XHP-2  [NA]
P1  B4B-XH-A(LF)(SN)  [conn_header_m_4pos_2p5_st]
P2  B2B-EH-A(LF)(SN)  [con_header_m_2pos_2p5_st]
R88  0.1R  [res0603]
R233  100R  [res0402]
R234  100R  [res0402]
R235  100R  [res0402]
R236  100R  [res0402]
S1  SXH-001T-P0.6
S2  SXH-001T-P0.6
S3  SXH-001T-P0.6
S4  SXH-001T-P0.6
S5  SXH-001T-P0.6
S6  SXH-001T-P0.6
sheet 16_FTDI_USB
C1  18pF  [cap0402]
C4  18pF  [cap0402]
C7  4.7uF  [cap0402]
C8  0.1uF  [cap0402]
C9  0.1uF  [cap0402]
C10  4.7uF  [cap0402]
C14  10uF  [cap0603]
C93  0.1uF  [cap0603]
C94  10uF  [cap0603]
C95  0.1uF  [cap0603]
C96  0.1uF  [cap0402]
C97  0.1uF  [cap0402]
C98  0.1uF  [cap0402]
C99  0.1uF  [cap0402]
C108  10uF  [cap0603]
C109  0.1uF  [cap0402]
C110  0.1uF  [cap0402]
C111  0.1uF  [cap0402]
C124  10uF  [cap0603]
D1  GREEN  [led_0603]
D11  DIODE_SUPPRESSOR ESD 30VDC 0402  [ESD0402]
D13  ESDR0502NMUTAG  [UDFN-6]
FB2  FB_220  [FB0603]
FB3  FB_220  [FB0603]
FB4  DNP  [FB0603]
FB38  DNP  [FB0603]
FB39  FB_220  [FB0603]
FTDI_TP1  FTDI_TP1  [TP_50]
FTDI_TP2  FTDI_TP2  [TP_50]
J5  61300311121  [conn_header_3pos]
J7  61300311121  [conn_header_3pos]
J8  2172034-1  [2172034-1]
J9  68000-408HLF  [8PINSTICK]
R1  10K  [res0603]
R2  10K  [res0603]
R3  2.2K  [res0603]
R4  10K  [res0603]
R5  0R  [res0402]
R6  0R  [res0402]
R7  0R  [res0402]
R8  330R  [res0603]
R9  0R  [res0603]
R15  4.7K  [res0603]
R16  10K  [res0603]
R17  DNP  [res0402]
R18  DNP  [res0402]
R19  DNP  [res0402]
R23  4.7K  [res0603]
R24  0R  [res0603]
R25  12K  [res0603]
R31  0R  [res0603]
R38  100R  [res0402]
R52  4.7K  [res0603]
R54  4.7K  [res0603]
R59  0R  [res0603]
R60  2.2K  [res0603]
R61  4.7K  [res0603]
R62  4.7K  [res0603]
R63  4.7K  [res0603]
R64  DNP  [res0603]
R66  33R  [res0402]
R67  33R  [res0402]
R68  33R  [res0402]
R143  DNP  [res0603]
SW1  MJTP1250  [SW_TH2]
U1  12MHz  [osc_32x25_4pin_25mhz]
U2  93LC56C-ISN  [soic_8_150mil]
U3  FT2232HQ  [QFN50P900X900X100-65N]
sheet 19_PS-5V,1V
1V0_D  1V0_D  [TP_50]
5V0_D  5V0_D  [TP_50]
12V0_D  12V0_D  [TP_50]
C15  330uF  [cap2917]
C17  10uF  [cap0603]
C18  0.1uF  [cap0402]
C19  4.7uF  [cap0603]
C20  0.022uF  [cap0603]
C21  10uF  [cap0603]
C22  0.1uF  [cap0402]
C23  0.1uF  [cap0402]
C24  0.047uF  [CAP0603]
C25  0.1uF  [cap0402]
C26  10uF  [cap0603]
C27  330uF  [cap2917]
C29  330uF  [cap2917]
C30  0.047uF  [cap0603]
C32  10uF  [cap0603]
C33  10uF  [cap0603]
C38  330uF  [cap2917]
C47  2.2uF  [CAP0402]
C48  0.1uF  [cap0402]
C50  0.01uF  [cap0603]
C167  0.1uF  [cap0402]
C169  0.1uF  [cap0402]
C174  0.1uF  [cap0402]
C176  0.1uF  [cap0402]
C177  0.1uF  [cap0402]
C178  0.1uF  [cap0402]
C179  0.1uF  [cap0402]
C182  0.1uF  [cap0402]
C183  0.1uF  [cap0402]
C184  10uF  [cap0603]
C193  0.1uF  [cap0402]
C194  0.1uF  [cap0402]
C195  2.2uF  [CAP0402]
C196  0.1uF  [cap0402]
C197  0.1uF  [cap0402]
C199  0.1uF  [cap0402]
C201  0.1uF  [cap0402]
C204  2.2uF  [CAP0402]
C205  10uF  [cap0603]
C208  0.1uF  [cap0402]
C209  0.1uF  [cap0402]
C213  2.2uF  [CAP0402]
C214  2.2uF  [CAP0402]
C215  0.1uF  [cap0402]
C216  2.2uF  [CAP0402]
C219  0.1uF  [cap0402]
C221  0.1uF  [cap0402]
C223  0.1uF  [cap0402]
C225  0.1uF  [cap0402]
C226  0.1uF  [cap0402]
C227  0.1uF  [cap0402]
C228  0.1uF  [cap0402]
C229  0.1uF  [cap0402]
C230  0.1uF  [cap0402]
C231  10uF  [cap0603]
C232  0.1uF  [cap0402]
C233  0.1uF  [cap0402]
C234  0.1uF  [cap0402]
C235  0.1uF  [cap0402]
C236  0.1uF  [cap0402]
C237  2.2uF  [CAP0402]
C242  0.1uF  [cap0402]
C243  0.1uF  [cap0402]
C244  0.1uF  [cap0402]
C245  0.1uF  [cap0402]
C246  0.1uF  [cap0402]
C248  0.1uF  [cap0402]
C249  0.1uF  [cap0402]
C250  2.2uF  [CAP0402]
C251  0.1uF  [cap0402]
C252  2.2uF  [CAP0402]
C253  0.1uF  [cap0402]
C255  0.1uF  [cap0402]
C256  0.1uF  [cap0402]
C258  0.1uF  [cap0402]
C259  0.1uF  [cap0402]
C286  10uF  [cap0603]
C295  100uF  [cap1206]
C296  47uF  [cap1206]
C303  100uF  [cap1206]
C304  47uF  [cap1206]
C305  47uF  [cap0805]
C306  0.47uF  [CAP0402]
C311  0.047uF  [cap0603]
D14  GREEN  [led_0603]
D16  B320A-13-F  [diode_sma]
D17  5.1V  [sod-323]
D19  GREEN  [led_0603]
DGND  DGND  [TP_50]
DGND_1  DGND_1  [TP_PTH]
DGND_2  DGND_2  [TP_PTH]
DGND_3  DGND_3  [TP_PTH]
DGND_4  DGND_4  [TP_PTH]
DGND_5  DGND_5  [TP_PTH]
F1  C1Q 3  [fus1206]
FB7  FB_220  [FB0603]
FB11  180E  [FB0805]
FB16  FB_220  [FB0603]
FB22  FB_220  [FB0603]
J11  694106301002  [694106301002]
R65  1K  [res0603]
R70  1.2M  [res0603]
R71  1.11K  [res1206]
R72  12.7 k  [res0402]
R73  0R  [res0603]
R74  42.2 k  [res0402]
R75  0.1R  [res0603]
R76  5.9K  [res0603]
R84  1K  [res0603]
R97  0.1R  [res0603]
R101  0.1R  [res0603]
R245  5.9K  [res0603]
SW2  TS01AQE  [sw_500SSP1S1M6QEA]
U4  LMZ30604RKGT  [RKG39]
U5  LMZ22005TZ/NOPB  [to_pmod_7]
U8  IC_JEDI_D1_672  [FPGA-672]  (sections A,B,C,D,E,F,G,H,I,J,K,L,M,N,O)

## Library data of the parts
1V0_D 3V3_PCie 5V0_D 12V0_D B7_1 B7_2 DGND FTDI_TP1 FTDI_TP2 = TP_SMD: Component Type: Test Point
C8 C9 C18 C22 C25 C48 C75 C77 C79-C84 C96-C107 C109-C111 C133-C141 C148 C149 C153 C155-C157 C159 C165-C183 C185 C187-C189 C192-C194 C196-C202 C207-C212 C215 C217-C230 C232-C236 C238 C241-C246 C248 C249 C251 C253 C255 C256 C258 C259 C261 C262 C265 C267 C270 C272 C276-C278 C285 C287 = C_0.1uF_50V_CER_0402
C7 C10 C85-C92 C263 C264 C279 C280 C283 C284 C288 C289 = C_4.7uF_10V_Cer_0402
C143-C147 C150 C160 C164 C186 C191 = C_0.22uF_25V_CER_0201
CN1 = J_PCIe_EDGE_X4_3
D1 D7-D10 D14 D19 D36 = LED_GREEN_0603
FB2-FB4 FB7-FB10 FB14 FB16 FB21 FB22 FB27 FB31 FB32 FB34-FB51 = FB__220E_0603
J19 = J_Header_6POS_2.54mm
R75 R77 R78 R88 R97 R99 R101 R131 R132 = R_0.1R_0603
R137 = R_3.3K_0402_1%_0.063W
R9 R24 R31 R59 R73 R143 R184 = R_0R_0603
R15 R23 R52 R54 R61-R63 R144-R183 R185-R187 R192 R195 R200 = R_4.7K_0603
R202 R204 R206 R207 = R_976R_0402
R205 R211 R213 R214 = R_100R_0201
R208-R210 R212 = R_1.15K_0402
U15 = Y_1.1328Mhz_6_SMD
C112-C119 = C_22uF_25V_CER_0805
C120-C123 C125-C132 = C_10uF_CER_50V_1206
C14 C17 C26 C31-C33 C36 C37 C66 C67 C94 C108 C124 C161 C184 C205 C231 C239 C286 C294 C297 = C_10uf_CER_25V_0603: CAP CER 10UF 25V X5R 0603
J10 J12 J16 J17 = J_SFPCONN_1888247-1: Component Type: SFP Connector
C47 C154 C195 C204 C213 C214 C216 C237 C250 C252 C271 = C_2.2uF_CER_25V_0402
Q8 Q10 Q12 Q14 Q15 = TRANS_NPN_BC847C_SOT-23
R26-R29 = R_470R_0402_1%_0.063W
R64 R65 R84 R253 R258 R262 R266 = R_1K_0603
R256 R260 R264 R268 = R_10K_0402_5%_0.1W_Au
C50 C142 = C_0.01uF_50V_CER_0603
D11 D37-D41 = DIODE_SUPPRESSOR_ESD_30VDC_0402
J13 = 1X4Shield: Component Type: SFP Cage Connector; MSL: 1; Manufacturer: TE Connectivity AMP Connectors; ROHS/NON-ROHS: ROHS
R38 R199 = R_100R_0402
R271 R272 = R_33R_0402_1%_0.1W
SW4 = TMP_190930: Manufacturer Part No: 219-5LPST
U14 = Y_200Mhz_LVDS_1: XTAL OSC XO 125.0000MHZ LVDS SMD; Manufacturer Part No: XLL536125.000000I; TOLERANCE: ±25ppm
J55 = CONN_JUMPER_2POS_2.54MM_ST
J56 = CONN_SHUNT_2POS_2.54MM
R5-R7 R17-R19 R188-R191 R193 R198 R203 = R_0R_0402_0.063W
R196 R197 R201 = R_22R_0402_1%_0.1W_Au
R270 = R_1K_0402_1%_0.1W_Au
C281 C282 = C_30pF_16V_CER_0
C291 C292 = C_30pF_16V_CER_0: VOLTAGE RATED: 25V
J53 = CONN_RCPT_4POS_2.5MM
J54 = CONN_RCPT_4POS_0.5MM
P1 = CONN_HEADER_4POS_2.5MM
P2 = CON_HEADER_2POS_2.5MM
R233-R236 = R_100R_0402_1%_0.1W
S1-S6 = Crimping_Pin_SXH
C1 C4 = C_18pF_50V_CER_0402: CAP CER 18PF 50V C0G/NPO 0402
C93 C95 = C_0.1uF_50V_CER_0603
D13 = TVS_DIODE_5.5V_ESDR0502NMUTAG
J5 J7 = J_CONN_Header_3_POS_VERT_2.54mm
J8 = USB_2_0.0_2172034-1
J9 = P_8PINS_2.54mm
R1 R2 R4 R16 = R_10K_0603
R3 R60 = R_2.2K_0603
R8 = R_330R_0603
R25 = R_12K_0603
R66-R68 = R_33R_0402
SW1 = SWITCH_TACTILE_SPST-NO_0.05A_12
U1 = Y_0.000MAAJ-T
U2 = IC_93LC56C-ISN_8-SOIC
U3 = IC_FT2232HQ-REEL_0: IC USB HS DUAL UART/FIFO 64-QFN
C15 C27 C29 C38 = C_330uF_10V_Tan_2917: MSL: 1
C19 = C_4.7uF_25V_CER_0603
C20 = C_0.022uF_50V_CER_0603
C21 = C_10uF_16V_Cer_0603
C23 = C_0.1uF_25V_Cer-0402
C24 C30 C311 = AEC_C_0.047uF_CER_50V_0603
C295 C303 = C_100uF_10V_Cer_1206
C296 C304 = C_47uF_1206_25V
C305 = C_47uF_10V_Cer_0805: Alternate PART NO: GRM21BR61A476ME15K
C306 = C_0.47uF_10V_CER_0402
D16 = DIODE_SCHOTTKY_20V_3A_SMD_0
D17 = TMP_164612
DGND_1-DGND_5 = TP_TH
F1 = F_10A_SMD: FUSE BOARD MOUNT 3A 125VAC 63VDC; Manufacturer: Bel Fuse Inc.; VOLTAGE RATED: 63VDC
FB11 = FB_180E_0805: ROHS/NON-ROHS: ROHS
J11 = J_JACK_2.10mm: TEMP: -40°C ~ 85°C
R70 = R_1.2M_0603
R71 = R_1.11K_1206
R72 = R_12.7K_0402
R74 = R_42.2K_0402
R76 R245 = R_5.9K_0603
SW2 = conn_0: SWITCH SLIDE SPDT 5A 120V; Component Type: Switch; MSL: 1 (Unlimited); Manufacturer: E-Switch; Manufacturer Part No: 500SSP1S1M6QEA; ROHS/NON-ROHS: ROHS; TEMP: -30°C ~ 85°C; VOLTAGE RATED: 28V
U4 = VR_LMZ30604RKGT_39-B1QFN
U5 = VR__LMZ22005TZ_NOPB_TO-PMOD-7: Alternate Part No: LMZ22003TZE/NOPB
U8 = IC_JEDI_D1_672

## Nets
1V8_LDO: FB14.1 FB16.1 FB22.1 FB31.1 FB32.1 FB34.1 FB35.1 FB36.1 FB37.1 FB48.1 FB49.1 FB50.1 FB51.1 ; also on sheet 8 21
1V8_OUT: FB4.1 R77.1 ; also on sheet 9 21
1V_LDO: FB21.1 R99.1 ; also on sheet 21
3V3_OUT: C94.1 C95.1 C98.1 C99.1 C108.1 C109.1 C111.1 C125.1 C126.1 C127.1 C128.1 C129.1 C130.1 C131.1 C132.1 C133.1 C134.1 C135.1 C136.1 C137.1 C138.1 C139.1 C140.1 C141.1 C142.1 FB2.1 FB3.1 FB40.2 FB41.2 FB42.2 FB43.2 FB44.2 FB45.2 FB46.2 FB47.2 J9.1 R1.1 R2.1 R4.1 R8.2 R23.1 R26.1 R27.1 R28.1 R29.1 R52.1 R54.1 R61.1 R62.1 R63.1 R78.1 R144.1 R145.1 R146.1 R148.1 R149.1 R150.1 R151.1 R153.1 R154.1 R155.1 R156.1 R158.1 R159.1 R160.1 R161.1 R163.1 R164.1 R165.1 R166.1 R167.1 R169.1 R170.1 R171.1 R172.1 R174.1 R175.1 R176.1 R177.1 R179.1 R180.1 R181.1 R182.1 R185.1 U2.6(ORG) U2.8(VCC) U3.20(VCCIO) U3.31(VCCIO__1) U3.42(VCCIO__2) U3.50(VREGIN) U3.56(VCCIO__3) U14.1(E/D) U14.6(VDD) ; also on sheet 2 6 7 8 12 21 22
3V3_PCIe: 3V3_PCie.1 CN1.A9(A9_3V3) CN1.A10(A10_3V3) CN1.B8(B8_3V3)
5V: 5V0_D.1 C15.1 C22.1 C24.1 C38.1 C305.1 FB11.1 FB38.1 R65.1 R76.1 R84.1 U5.7(VOUT1) ; also on sheet 1 8 21
12V_IN: 12V0_D.1 C25.1 C26.1 C30.1 C32.1 C33.1 C311.1 F1.2 R74.1 U5.1(VIN1) ; also on sheet 7
12V_IN_PCIE: CN1.A2(A2_12V) CN1.A3(A3_12V) CN1.B1(B1_12V) CN1.B2(B2_12V) CN1.B3(B3_12V) R137.1 SW2.1(T1)
GND: C1.2 C4.2 C7.2 C8.2 C9.2 C10.2 C14.2 C15.2 C17.2 C18.2 C19.2 C20.2 C21.2 C22.2 C23.2 C24.2 C25.2 C26.2 C27.2 C29.2 C30.2 C31.2 C32.2 C33.2 C36.2 C37.2 C38.2 C47.2 C48.2 C50.2 C66.2 C67.2 C93.2 C94.2 C95.2 C96.2 C97.2 C98.2 C99.2 C100.2 C101.2 C102.2 C103.2 C104.2 C105.2 C106.2 C107.2 C108.2 C109.2 C110.2 C111.2 C112.2 C113.2 C114.2 C115.2 C116.2 C117.2 C118.2 C119.2 C120.2 C121.2 C122.2 C123.2 C124.2 C125.2 C126.2 C127.2 C128.2 C129.2 C130.2 C131.2 C132.2 C133.2 C134.2 C135.2 C136.2 C137.2 C138.2 C139.2 C140.2 C141.2 C142.2 C148.2 C149.2 C154.2 C155.2 C157.2 C159.2 C161.2 C165.2 C166.2 C167.2 C169.2 C171.2 C172.2 C173.2 C174.2 C175.2 C176.2 C177.2 C178.2 C179.2 C180.2 C181.2 C182.2 C183.2 C184.2 C187.2 C188.2 C189.2 C192.2 C193.2 C194.2 C195.2 C196.2 C197.2 C198.2 C199.2 C201.2 C204.2 C205.2 C208.2 C209.2 C210.2 C211.2 C212.2 C213.2 C214.2 C215.2 C216.2 C218.2 C219.2 C220.2 C221.2 C222.2 C223.2 C224.2 C225.2 C226.2 C227.2 C228.2 C229.2 C230.2 C231.2 C232.2 C233.2 C234.2 C235.2 C236.2 C237.2 C239.2 C241.2 C242.2 C243.2 C244.2 C245.2 C246.2 C248.2 C249.2 C250.2 C251.2 C252.2 C253.2 C255.2 C256.2 C258.2 C259.2 C271.2 C272.2 C276.2 C277.2 C286.2 C294.2 C295.2 C296.2 C297.2 C303.2 C304.2 C305.2 C306.2 C311.2 CN1.A4(A4_GND) CN1.A12(A12_GND) CN1.A15(A15_GND) CN1.A18(A18_GND) CN1.A20(A20_GND) CN1.A23(A23_GND) CN1.A24(A24_GND) CN1.A27(A27_GND) CN1.A28(A28_GND) CN1.A31(A31_GND) CN1.B4(B4_GND) CN1.B7(B7_GND) CN1.B13(B13_GND) CN1.B16(B16_GND) CN1.B18(B18_GND) CN1.B21(B21_GND) CN1.B22(B22_GND) CN1.B25(B25_GND) CN1.B26(B26_GND) CN1.B29(B29_GND) CN1.B32(B32_GND) D11.2(A2) D13.1(GND) D14.K D16.1(Anode) D17.1(A) D19.K D36.K D37.2(A2) D38.2(A2) D39.2(A2) D40.2(A2) D41.2(A2) DGND.1 DGND_1.1 DGND_2.1 DGND_3.1 DGND_4.1 DGND_5.1 J8.5(GND) J9.7 J10.1(VEET1) J10.10(VEER2) J10.11(VEER3) J10.14(VEER4) J10.17(VEET2) J10.20(VEET3) J11.2(GND) J11.3(GND) J12.1(VEET1) J12.10(VEER2) J12.11(VEER3) J12.14(VEER4) J12.17(VEET2) J12.20(VEET3) J16.1(VEET1) J16.10(VEER2) J16.11(VEER3) J16.14(VEER4) J16.17(VEET2) J16.20(VEET3) J17.1(VEET1) J17.10(VEER2) J17.11(VEER3) J17.14(VEER4) J17.17(VEET2) J17.20(VEET3) J19.5 Q8.2(E) Q10.2(E) Q12.2(E) Q14.2(E) Q15.2(E) R16.2 R25.1 R60.1 R70.2 R71.2 R72.2 R73.1 R143.2 R147.2 R152.2 R157.2 R162.2 R168.2 R173.2 R178.2 R183.2 R203.2 R245.2 R256.2 R260.2 R264.2 R268.2 SW1.1 SW4.6(A6) SW4.7(A7) SW4.8(A8) SW4.9(B8) SW4.10(B7) U1.2(GND2) U1.4(GND4) U2.5(VSS) U3.1(GND) U3.5(GND__1) U3.10(AGND) U3.11(GND__2) U3.13(TEST) U3.15(GND__3) U3.25(GND__4) U3.35(GND__5) U3.47(GND__6) U3.51(GND__7) U3.65(GND__8) U4.1(AGND) U4.5(AGND_1) U4.7(STSEL) U4.29(AGND_2) U4.33(AGND_3) U4.34(AGND_4) U4.37(PGND) U5.4(AGND) U5.8(PGND) U8.A4(VSSSDQ) U8.A7(VSSSDQ) U8.A10(VSSSDQ) U8.A13(VSSSDQ) U8.A16(VSSSDQ) U8.A19(VSSSDQ) U8.A20(VSSSDQ) U8.A23(VSSSDQ) U8.AB21(VSS) U8.AC5(VSS) U8.AC8(VSS) U8.AC10(VSS) U8.AC14(VSS) U8.AC17(VSS) U8.AD2(VSSADC) U8.AD24(VSS) U8.AE20(VSS) U8.B2(VSSSDQ) U8.B3(VSSSDQ) U8.B5(VSSSDQ) U8.B6(VSSSDQ) U8.B8(VSSSDQ) U8.B9(VSSSDQ) U8.B11(VSSSDQ) U8.B12(VSSSDQ) U8.B14(VSSSDQ) U8.B15(VSSSDQ) U8.B17(VSSSDQ) U8.B18(VSSSDQ) U8.B21(VSSSDQ) U8.B22(VSSSDQ) U8.B24(VSSSDQ) U8.B25(VSSSDQ) U8.C2(VSSSDQ) U8.C3(VSSSDQ) U8.C5(VSSSDQ) U8.C7(VSSSDQ) U8.C9(VSSSDQ) U8.C11(VSSSDQ) U8.C13(VSSSDQ) U8.C15(VSSSDQ) U8.C17(VSSSDQ) U8.C19(VSSSDQ) U8.C20(VSSSDQ) U8.C23(VSSSDQ) U8.C25(VSSSDQ) U8.D1(VSSSDQ) U8.D4(VSSSDQ) U8.D6(VSSSDQ) U8.D7(VSSSDQ) U8.D8(VSSSDQ) U8.D10(VSSSDQ) U8.D12(VSSSDQ) U8.D14(VSSSDQ) U8.D16(VSSSDQ) U8.D20(VSSSDQ) U8.D21(VSSSDQ) U8.D22(VSSSDQ) U8.D23(VSSSDQ) U8.D24(VSSSDQ) U8.D26(VSSSDQ) U8.E2(VSSSDQ) U8.E3(VSSSDQ) U8.E5(VSSSDQ) U8.E14(VSSSDQ) U8.E23(VSSSDQ) U8.E25(VSSSDQ) U8.F2(VSSSDQ) U8.F4(VSSSDQ) U8.F5(VSSSDQ) U8.F6(VSSSDQ) U8.F7(VSSSDQ) U8.F8(VSSSDQ) U8.F10(VSSSDQ) U8.F13(VSSSDQ) U8.F14(VSSSDQ) U8.F18(VSSSDQ) U8.F21(VSSSDQ) U8.F23(VSSSDQ) U8.F24(VSSSDQ) U8.F25(VSSSDQ) U8.G1(VSSSDQ) U8.G3(VSSSDQ) U8.G10(VSSSDQ) U8.G12(VSSSDQ) U8.G14(VSSSDQ) U8.G16(VSSSDQ) U8.G23(VSSSDQ) U8.G26(VSSSDQ) U8.H14(VSSSDQ) U8.H18(VSSSDQ) U8.H24(VSSSDQ) U8.H25(VSSSDQ) U8.J4(VSS) U8.J11(VSSSDQ) U8.J12(VSSSDQ) U8.J17(VSSSDQ) U8.K13(VSSSDQ) U8.K23(VSS) U8.L4(VSS) U8.L11(VSS) U8.L13(VSS) U8.L16(VSSSDQ) U8.M11(VSS) U8.M13(VSS) U8.M15(VSS) U8.M17(VSS) U8.M21(VSS) U8.N10(VSS) U8.N12(VSS) U8.N14(VSS) U8.N16(VSS) U8.P4(VSS) U8.P11(VSS) U8.P13(VSS) U8.P15(VSS) U8.P17(VSS) U8.R10(VSS) U8.R12(VSS) U8.R14(VSS) U8.R16(VSS) U8.R24(VSS) U8.T11(VSS) U8.T13(VSS) U8.T15(VSS) U8.T17(VSS) U8.U5(VSS) U8.U9(VSS) U8.U12(VSS) U8.U14(VSS) U8.U16(VSS) U8.U21(VSS) U8.V11(VSS) U8.V13(VSS) U8.Y3(VSS) U8.Y24(VSS) U14.3(GND) U15.3(GND) ; also on sheet 1 2 6 7 8 9 12 21 22
GND_EARTH: J8.SH1(SHELL) J8.SH2(SHELL__1) J13.1 J13.2 J13.3 J13.4 J13.5 J13.6 J13.7 J13.8 J13.9 J13.10 J13.11 J13.12 J13.13 J13.14 J13.15 J13.16 J13.17 J13.18 J13.19 J13.20 J13.21 J13.22 J13.23 J13.24 J13.25 J13.26 J13.27 J13.28 J13.29 J13.30 J13.31 J13.32 J13.33 J13.34 ; also on sheet 8
VBUS_5V: C93.1 D13.6(VBUS) FB38.2 J8.1(VBUS) R15.1
VCC_CORE: C21.1 C23.1 FB7.2 R75.1 ; also on sheet 21
VCC_FT_VPHY: C7.1 C8.1 FB2.2 U3.4(VPHY)
VCC_FT_VPLL: C9.1 C10.1 FB3.2 U3.9(VPLL)
VCCAUX_1V8: C167.1 C169.1 C177.1 C178.1 C195.1 C196.1 C243.1 C246.1 C251.1 C252.1 C253.1 C255.1 C256.1 C286.1 R97.2 U8.L17(VCCAUX) U8.M10(VCCAUX) U8.R17(VCCAUX) U8.U10(VCCAUX) U8.U15(VCCAUXH4) U8.U17(VCCAUXH5) U8.V9(VCCAUXH3) U8.V10(VCCAUXH3) U8.V15(VCCAUXH4) U8.V17(VCCAUXH5)
VCCAUXA_1V8: C47.1 C48.1 C50.1 C225.1 R101.2 U8.L12(VCCAUXA) U8.L14(VCCAUXA)
VCCAUXSDQ0: C81.2 C82.2 C83.2 C84.2 C85.1 C86.1 C87.1 C88.1 R131.2 U8.J16(VCCAUXSDQ0)
VCCAUXSDQ1: C262.2 C263.1 C278.2 C279.1 C283.1 C285.2 C287.2 C288.1 R132.2 U8.J13(VCCAUXSDQ1)
VCCCORE: C174.1 C176.1 C179.1 C182.1 C183.1 C184.1 C193.1 C194.1 C197.1 C199.1 C201.1 C204.1 C205.1 C208.1 C209.1 C213.1 C214.1 C215.1 C216.1 C219.1 C221.1 C223.1 C226.1 C227.1 C228.1 C229.1 C230.1 C231.1 C232.1 C233.1 C234.1 C235.1 C236.1 C237.1 C242.1 C244.1 C245.1 C248.1 C249.1 C250.1 C258.1 C259.1 R75.2 U8.L10(VCC) U8.L15(VCC) U8.M12(VCC) U8.M14(VCC) U8.N11(VCC) U8.N13(VCC) U8.N15(VCC) U8.N17(VCC) U8.P10(VCC) U8.P12(VCC) U8.P14(VCC) U8.P16(VCC) U8.R11(VCC) U8.R13(VCC) U8.R15(VCC) U8.T9(VCCECLK) U8.T10(VCC) U8.T12(VCC) U8.T14(VCC) U8.T16(VCC) U8.U11(VCC) U8.U13(VCC) U8.V12(VCCECLK) U8.V14(VCCECLK) U8.V16(VCCECLK)
VCCIO2_1V8: FB8.1 R77.2
VCCIO2_3V3: FB9.1 R78.2
VCCIO5_1V8: FB10.1 R186.1 R187.1 R192.1 R195.1 R200.1 ; also on sheet 21
VCCIO7_3V3: FB27.1 ; also on sheet 21
VCCPLLSD0: C89.1 C153.1 FB34.2 U8.F22(VCCPLLSD0)
VCCPLLSD1: C90.1 C156.1 FB35.2 U8.G22(VCCPLLSD1)
VCCPLLSD2: C91.1 C168.1 FB36.2 U8.F19(VCCPLLSD2)
VCCPLLSD3: C92.1 C170.1 FB37.2 U8.E18(VCCPLLSD3)
VCCPLLSD4: C185.1 C264.1 FB48.2 U8.E16(VCCPLLSD4)
VCCPLLSD5: C202.1 C289.1 FB51.2 U8.H15(VCCPLLSD5)
VCCPLLSD6: C200.1 C280.1 FB49.2 U8.F15(VCCPLLSD6)
VCCPLLSD7: C238.1 C284.1 FB50.2 U8.F12(VCCPLLSD7)
VCCSD: C161.1 C165.1 C166.1 C171.1 C172.1 C173.1 C175.1 C180.1 C181.1 C187.1 C188.1 C192.1 C198.1 C210.1 C211.1 C212.1 C218.1 C220.1 C222.1 C224.1 C239.1 C294.1 R99.2 U8.F16(VCCSD4) U8.F17(VCCSD4) U8.G13(VCCSD7) U8.G15(VCCSD5) U8.G17(VCCSD3) U8.G18(VCCSD1) U8.G19(VCCSD0) U8.H13(VCCSD7) U8.H16(VCCSD5) U8.H17(VCCSD3) U8.H19(VCCSD0) U8.J14(VCCSD6) U8.J18(VCCSD1) U8.K14(VCCSD6) U8.K16(VCCSD2) U8.K17(VCCSD2)
VDD_2V5: C241.1 U15.1(OE) U15.6(VDD) ; also on sheet 8
DPLL_CLKOUT_2N: C267.2 ; also on sheet 7
DPLL_CLKOUT_2P: C270.2 ; also on sheet 7
DPLL_CSB: U8.V7(PR47B) ; also on sheet 7
DPLL_FDEC: U8.V6(PR53B) ; also on sheet 7
DPLL_FINC: U8.W7(PR55A) ; also on sheet 7
DPLL_FLEXIO_1: U8.W4(PR56B) ; also on sheet 7
DPLL_FLEXIO_2: U8.W5(PR56A) ; also on sheet 7
DPLL_I2C_SCL: U8.U6(PR46A/PCLKT2_2) ; also on sheet 2 7
DPLL_I2C_SDA: U8.U7(PR46B) ; also on sheet 2 7
DPLL_I2C_SPI0: U8.V8(PR47A) ; also on sheet 7
DPLL_INTRB: U8.V2(PR49B) ; also on sheet 7
DPLL_OEB: U8.V3(PR51A) ; also on sheet 7
DPLL_PLL_SEL0: U8.V4(PR51B) ; also on sheet 7
DPLL_PLL_SEL1: U8.V5(PR53A) ; also on sheet 7
DPLL_SDO: U8.V1(PR49A) ; also on sheet 7
EP_PCIe_RXD0_N: CN1.B15(PETn0) U8.G25(SD0_RXDN)
EP_PCIe_RXD0_P: CN1.B14(PETp0) U8.G24(SD0_RXDP)
EP_PCIe_RXD1_N: CN1.B20(PETn1) U8.D25(SD1_RXDN)
EP_PCIe_RXD1_P: CN1.B19(PETp1) U8.E24(SD1_RXDP)
EP_PCIe_RXD2_N: CN1.B24(PETn2) U8.B23(SD2_RXDN)
EP_PCIe_RXD2_P: CN1.B23(PETp2) U8.C24(SD2_RXDP)
EP_PCIe_RXD3_N: CN1.B28(PETn3) U8.C22(SD3_RXDN)
EP_PCIe_RXD3_P: CN1.B27(PETp3) U8.C21(SD3_RXDP)
EP_PCIe_TXD0_N: C146.1 CN1.A17(PERn0)
EP_PCIe_TXD0_P: C145.1 CN1.A16(PERp0)
EP_PCIe_TXD1_N: C150.1 CN1.A22(PERn1)
EP_PCIe_TXD1_P: C147.1 CN1.A21(PERp1)
EP_PCIe_TXD2_N: C164.1 CN1.A26(PERn2)
EP_PCIe_TXD2_P: C160.1 CN1.A25(PERp2)
EP_PCIe_TXD3_N: C191.1 CN1.A30(PERn3)
EP_PCIe_TXD3_P: C186.1 CN1.A29(PERp3)
F_125Mhz_N: R199.2 U8.W23(PB10B/PCLKC5_1/ADC_CN2/COMP3N) U14.5(OUT#)
F_125Mhz_P: R199.1 U8.W24(PB10A/PCLKT5_1/ADC_CP2/COMP3P) U14.4(OUT)
F_FLASH_CS#: R191.2 ; also on sheet 12
F_FLASH_DQ0: R193.2 ; also on sheet 12
F_FLASH_DQ1: R190.2 ; also on sheet 12
F_FLASH_DQ2: R189.2 ; also on sheet 12
F_FLASH_DQ3: R188.2 ; also on sheet 12
F_FLASH_MCLK: R197.2 ; also on sheet 12
F_PCIe_EC_100Mhz_CLK_N: C144.2 CN1.A14(REFCLK-)
F_PCIe_EC_100Mhz_CLK_P: C143.2 CN1.A13(REFCLK+)
F_PCIe_EC_PRSNT#: J19.3 R184.1 R185.2 ; also on sheet 6
F_SFP1_ABS: J16.6(MOD_DEF0/ABS) R176.2 ; also on sheet 6
F_SFP1_I2C_SCL: J16.5(MOD_DEF1/SCL) R175.2 ; also on sheet 6
F_SFP1_I2C_SDA: J16.4(MOD_DEF2/SDA) R155.2 ; also on sheet 6
F_SFP1_LOS: J16.8(LOS) R177.2 ; also on sheet 6
F_SFP1_RX_N: J16.12(RD-) U8.C12(SD6_RXDN)
F_SFP1_RX_P: J16.13(RD+) U8.B13(SD6_RXDP)
F_SFP1_TX_DISABLE: J16.3(TX_DISABLE) R154.2 ; also on sheet 6
F_SFP1_TX_FAULT: J16.2(TX_FAULT) R174.2 ; also on sheet 6
F_SFP1_TX_N: J16.19(TD-) U8.A11(SD6_TXDN)
F_SFP1_TX_P: J16.18(TD+) U8.A12(SD6_TXDP)
F_SFP2_ABS: J17.6(MOD_DEF0/ABS) R181.2 ; also on sheet 6
F_SFP2_I2C_SCL: J17.5(MOD_DEF1/SCL) R180.2 ; also on sheet 6
F_SFP2_I2C_SDA: J17.4(MOD_DEF2/SDA) R160.2 ; also on sheet 6
F_SFP2_LOS: J17.8(LOS) R182.2 ; also on sheet 6
F_SFP2_RX_N: J17.12(RD-) U8.C10(SD7_RXDN)
F_SFP2_RX_P: J17.13(RD+) U8.B10(SD7_RXDP)
F_SFP2_TX_DISABLE: J17.3(TX_DISABLE) R159.2 ; also on sheet 6
F_SFP2_TX_FAULT: J17.2(TX_FAULT) R179.2 ; also on sheet 6
F_SFP2_TX_N: J17.19(TD-) U8.A8(SD7_TXDN)
F_SFP2_TX_P: J17.18(TD+) U8.A9(SD7_TXDP)
F_SFP3_ABS: J12.6(MOD_DEF0/ABS) R171.2 ; also on sheet 6
F_SFP3_I2C_SCL: J12.5(MOD_DEF1/SCL) R170.2 ; also on sheet 6
F_SFP3_I2C_SDA: J12.4(MOD_DEF2/SDA) R150.2 ; also on sheet 6
F_SFP3_LOS: J12.8(LOS) R172.2 ; also on sheet 6
F_SFP3_RX_N: J12.12(RD-) U8.V25(PB2B/LLC_GPLL0C_IN/CDR_RXN0/ADC_CN0/COMP1N)
F_SFP3_RX_P: J12.13(RD+) U8.V24(PB2A/LLC_GPLL0T_IN/CDR_RXP0/VREF5_1/ADC_CP0/COMP1P)
F_SFP3_TX_DISABLE: J12.3(TX_DISABLE) R149.2 ; also on sheet 6
F_SFP3_TX_FAULT: J12.2(TX_FAULT) R169.2 ; also on sheet 6
F_SFP3_TX_N: J12.19(TD-) U8.V26(PB6B)
F_SFP3_TX_P: J12.18(TD+) U8.U26(PB6A)
F_SFP4_ABS: J10.6(MOD_DEF0/ABS) R166.2 ; also on sheet 6
F_SFP4_I2C_SCL: J10.5(MOD_DEF1/SCL) R165.2 ; also on sheet 6
F_SFP4_I2C_SDA: J10.4(MOD_DEF2/SDA) R145.2 ; also on sheet 6
F_SFP4_LOS: J10.8(LOS) R167.2 ; also on sheet 6
F_SFP4_RX_N: J10.12(RD-) U8.V22(PB4B/PCLKC5_0/CDR_RXN1/ADC_CN1/COMP2N)
F_SFP4_RX_P: J10.13(RD+) U8.V23(PB4A/PCLKT5_0/CDR_RXP1/ADC_CP1/COMP2P)
F_SFP4_TX_DISABLE: J10.3(TX_DISABLE) R144.2 ; also on sheet 6
F_SFP4_TX_FAULT: J10.2(TX_FAULT) R164.2 ; also on sheet 6
F_SFP4_TX_N: J10.19(TD-) U8.AF24(PB44B)
F_SFP4_TX_P: J10.18(TD+) U8.AE24(PB44A)
F_SFP_161.1328Mhz_CLK_N: C217.2 U15.5(CLK-)
F_SFP_161.1328Mhz_CLK_P: C207.2 U15.4(CLK+)
F_TCK: J9.8 R60.2 R67.2 ; also on sheet 22
F_TDI: J9.3 R61.2 R66.2 ; also on sheet 22
F_TDO: J9.2 R62.2 U3.18(ADBUS2) ; also on sheet 22
F_TMS: J9.6 R63.2 R68.2 ; also on sheet 22
FMC_HA17_N_CC: U8.AF25(PB42B) ; also on sheet 2
FMC_HA17_P_CC: U8.AE26(PB42A) ; also on sheet 2
FMC_OCXO_EN: U8.AA2(PR64A) ; also on sheet 2
FMC_PG_FPGA: U8.K19(PL15B) ; also on sheet 2 7
FMC_PRST_M2C_L: U8.K21(PL17A) ; also on sheet 2
FMC_TCK: R201.2 ; also on sheet 2 7
FMC_TDI: U8.N22(PL31B) ; also on sheet 2 7
FMC_TDO: U8.N21(PL33A) ; also on sheet 2 7
FMC_TMS: U8.N20(PL33B) ; also on sheet 2 7
FMC_ToD_IN: U8.J24(PL8B) ; also on sheet 7
FMC_ToD_OUT: U8.J23(PL10A) ; also on sheet 7
FPGA_CLKOUT_10MHz_N: R272.2 ; also on sheet 7
FPGA_CLKOUT_10MHz_P: R271.2 ; also on sheet 7
FPGA_DPLL_RESET_N: U8.W6(PR55B) ; also on sheet 7
FPGA_GNSS_RESET_N: R198.2 ; also on sheet 2
FPGA_PG_FMC: U8.L21(PL17B) ; also on sheet 2 7
FPGA_PPS_IN: U8.H20(PL3A/ULC_GPLL0T_IN) ; also on sheet 7
FPGA_PPS_OUT: U8.H22(PL4A) ; also on sheet 7
FTDI_EEPROM_CLK_FPGA: R18.2 R196.2
FTDI_EEPROM_CS_FPGA: R17.2 U8.L19(PL26B)
FTDI_EEPROM_DI_FPGA: R19.2 U8.L22(PL24B)
FTDI_I2C_SCL: R59.2 ; also on sheet 22
FTDI_I2C_SDA: R24.2 R31.2 ; also on sheet 22
FTDI_UART_RXD: J5.1 R9.1 ; also on sheet 22
FTDI_UART_TXD: J7.1 ; also on sheet 22
FTDI_VCORE_1V8: C96.1 C97.1 C110.1 C124.1 FB4.2 FB39.1 U3.12(VCORE) U3.37(VCORE__1) U3.64(VCORE__2)
GNSS_EXTINT0: U8.J26(PL6B) ; also on sheet 2
GNSS_EXTINT1: U8.J25(PL8A) ; also on sheet 2
GNSS_I2C_SCL: U8.J20(PL11B) ; also on sheet 2
GNSS_I2C_SDA: U8.J19(PL13A) ; also on sheet 2
GNSS_RX: U8.J21(PL11A) ; also on sheet 2
GNSS_TIME_PULSE_2: U8.K20(PL13B) ; also on sheet 2
GNSS_TX: U8.J22(PL10B) ; also on sheet 2
LED4: R253.1 ; also on sheet 22
LED5: R258.1 ; also on sheet 22
LED6: R262.1 ; also on sheet 22
LED7: R266.1 ; also on sheet 22
LLAb: U8.W3(PR58A) ; also on sheet 2
LLBb: U8.W2(PR58B) ; also on sheet 2
LLCb: U8.W1(PR60A) ; also on sheet 2
LLDb: U8.Y1(PR60B) ; also on sheet 2
PCIe_EC_PRSNT#1: CN1.A1(PRSNT#1) J19.2
PCIe_EC_PRSNT#2: CN1.B17(PRSNT#2) J19.1
PCIe_EC_PRSNT#3: CN1.B31(PRSNT2#) J19.4
PROGRAMN: J55.2 R64.2 ; also on sheet 12
PWRGD_1V: D19.A R84.2 U4.27(PWRGD)
RESET#: C14.1 R38.2 U3.14(~{RESET#})
SD0_REFRET: C81.1 C85.2 C89.2 C153.2 R202.2 U8.E22(SD0_REFRET)
SD0_REXT: R202.1 U8.E21(SD0_REXT)
SD1_REFRET: C83.1 C86.2 C90.2 C156.2 R204.2 U8.G21(SD1_REFRET)
SD1_REXT: R204.1 U8.G20(SD1_REXT)
SD2_REFRET: C82.1 C87.2 C91.2 C168.2 R206.2 U8.E19(SD2_REFRET)
SD2_REXT: R206.1 U8.D19(SD2_REXT)
SD3_REFRET: C84.1 C88.2 C92.2 C170.2 R207.2 U8.D18(SD3_REFRET)
SD3_REXT: R207.1 U8.C18(SD3_REXT)
SD4_REFRET: C185.2 C262.1 C263.2 C264.2 R208.2 U8.E17(SD4_REFRET)
SD4_REXT: R208.1 U8.D17(SD4_REXT)
SD4_RX_N_FMC_TX_N: U8.B19(SD4_RXDN) ; also on sheet 7
SD4_RX_P_FMC_TX_P: U8.B20(SD4_RXDP) ; also on sheet 7
SD4_TX_N_FMC_RX_N: C79.1 ; also on sheet 7
SD4_TX_P_FMC_RX_P: C80.1 ; also on sheet 7
SD5_REFRET: C202.2 C287.1 C288.2 C289.2 R210.2 U8.J15(SD5_REFRET)
SD5_REXT: R210.1 U8.K15(SD5_REXT)
SD5_RX_N_FMC_TX_N: U8.B16(SD5_RXDN) ; also on sheet 7
SD5_RX_P_FMC_TX_P: U8.C16(SD5_RXDP) ; also on sheet 7
SD5_TX_N_FMC_RX_N: C75.2 ; also on sheet 7
SD5_TX_P_FMC_RX_P: C77.2 ; also on sheet 7
SD6_REFRET: C200.2 C278.1 C279.2 C280.2 R209.2 U8.E15(SD6_REFRET)
SD6_REXT: R209.1 U8.D15(SD6_REXT)
SD7_REFRET: C238.2 C283.2 C284.2 C285.1 R212.2 U8.E12(SD7_REFRET)
SD7_REXT: R212.1 U8.E13(SD7_REXT)
SWITCH1: D37.1(A1) R186.2 SW4.1(A1) U8.AA23(PB28A)
SWITCH2: D38.1(A1) R187.2 SW4.2(A2) U8.AB22(PB26A)
SWITCH3: D39.1(A1) R192.2 SW4.3(A3) U8.AC22(PB38A)
SWITCH4: D40.1(A1) R195.2 SW4.4(A4) U8.AA22(PB26B)
SWITCH5: D41.1(A1) R200.2 SW4.5(A5) U8.W21(PB12B)
SyncE_RX_Clk_FMC_N: U8.AD22(PB46B/PCLKC5_3) ; also on sheet 7
SyncE_RX_Clk_FMC_P: U8.AC21(PB46A/PCLKT5_3) ; also on sheet 7
SyncE_TX_CLK_FPGA_N: C265.2 ; also on sheet 7
SyncE_TX_CLK_FPGA_P: C261.2 ; also on sheet 7
USB_D_N: D13.3(NC) D13.4(D-) J8.2(D-) U3.7(DM)
USB_D_P: D13.2(NC) D13.5(D+) J8.3(D+) U3.8(DP)
N11231127: R66.1 U3.17(ADBUS1)
N11231131: R67.1 U3.16(ADBUS0)
N11231133: R68.1 U3.19(ADBUS3)
N11231353: R25.2 U3.6(REF)
N11232635: R64.1 U3.24(ADBUS7)
N11233365: R4.2 R5.2 R17.1 U2.1(CS)
N11233392: R3.2 R7.2 R19.1 U2.3(DI)
N11233407: R1.2 R3.1 U2.4(DO)
N11233625: R2.2 R6.2 R18.1 U2.2(CLK)
N11235460: C1.1 U1.1(XiN) U3.2(OSCI)
N11235464: C4.1 U1.3(Xout) U3.3(OSCO)
N16887369: C17.1 C18.1 D16.2(Cathode) F1.1 SW2.2(P)
N16938603: FB39.2 U3.49(VREGOUT)
N16938967: R15.2 R16.1 U3.59(BCBUS7)
N16940191: FTDI_TP1.1 U3.60(~{PWREN#})
N16940207: FTDI_TP2.1 U3.36(~{SUSPEND#})
N16973398: J8.4(ID) R143.1
N17771975: 1V0_D.1 C19.1 C29.1 C295.1 C296.1 FB7.1 U4.8(VOUT) U4.9(VOUT_1) U4.10(VOUT_2) U4.11(VOUT_3) U4.12(VOUT_4) U4.13(VOUT_5) U4.14(VOUT_6) U4.36(SENSE+) U4.38(VOUT_7)
N17772012: R70.1 U4.4(RT/CLK)
N17772020: R245.1 U4.35(VADJ)
N17772036: C20.1 U4.6(SS/TR)
N17772060: C27.1 C303.1 C304.1 FB11.2 U4.30(VIN) U4.31(VIN_1) U4.32(VIN_2)
N17772319: U4.17(PH) U4.18(PH_1) U4.19(PH_2) U4.20(PH_3) U4.21(PH_4) U4.22(PH_5) U4.23(PH_6) U4.24(PH_7) U4.25(PH_8) U4.39(PH_9)
N17811699: J5.2 U3.39(BDBUS1)
N17811707: R31.1 U3.40(BDBUS2)
N17811724: J7.3 R54.2 R59.1
N17811997: J7.2 U3.38(BDBUS0)
N18159248: FB14.2 R88.1
N18159250: C37.1 C277.1 R88.2 U8.AC3(VCCADC18)
N18182140: J11.1(+5V) SW2.3(T2)
N18574948: R73.2 U5.2(SYNC)
N18575298: D17.2(K) R72.1 R74.2 U5.3(EN)
N18576820: R71.1 R76.2 U5.5(FB)
N18603809: J16.7(RATE_SELECT0) R156.2 R157.1
N18603811: J16.9(RATE_SELECT1) R158.2 R178.1
N18604069: C101.1 C119.1 C122.1 FB46.1 J16.15(VCCR)
N18604095: C105.1 C115.1 FB42.1 J16.16(VCCT)
N18605551: J17.7(RATE_SELECT0) R161.2 R162.1
N18605553: J17.9(RATE_SELECT1) R163.2 R183.1
N18605811: C102.1 C117.1 C123.1 FB47.1 J17.15(VCCR)
N18605837: C107.1 C114.1 FB43.1 J17.16(VCCT)
N18645444: CN1.A11(PERST#) R184.2
N18656886: C36.1 C148.1 C149.1 C154.1 C157.1 FB10.2 U8.AA21(VCCIO5) U8.AC23(VCCIO5) U8.Y23(VCCIO5)
N18667256: C66.1 C67.1 C155.1 C159.1 FB27.2 U8.K22(VCCIO7) U8.M20(VCCIO7)
N18672800: FB22.2 R101.1
N18672920: FB16.2 R97.1
N18696445: C145.2 U8.F26(SD0_TXDP)
N18696466: C146.2 U8.E26(SD0_TXDN)
N18696487: C147.2 U8.C26(SD1_TXDP)
N18696508: C150.2 U8.B26(SD1_TXDN)
N18696529: C160.2 U8.A25(SD2_TXDP)
N18696550: C164.2 U8.A24(SD2_TXDN)
N18696571: C186.2 U8.A22(SD3_TXDP)
N18696592: C191.2 U8.A21(SD3_TXDN)
N18696908: C143.1 R205.2 U8.F20(SDQ0_REFCLKP)
N18696914: C144.1 R205.1 U8.E20(SDQ0_REFCLKN)
N18697309: C207.1 R211.2 U8.C14(SDQ1_REFCLKP)
N18697310: C217.1 R211.1 U8.D13(SDQ1_REFCLKN)
N18716473: C189.1 C297.1 FB21.2 U8.M16(VCCSDCK)
N18749315: J12.7(RATE_SELECT0) R151.2 R152.1
N18749317: J12.9(RATE_SELECT1) R153.2 R173.1
N18749570: C100.1 C116.1 C121.1 FB45.1 J12.15(VCCR)
N18749596: C104.1 C113.1 FB41.1 J12.16(VCCT)
N18793757: C265.1 R213.1 U8.E11(SD_EXT0_REFCLKN)
N18793758: C261.1 R213.2 U8.D11(SD_EXT0_REFCLKP)
N18793759: C270.1 R214.2 U8.E10(SD_EXT1_REFCLKP)
N18793760: C267.1 R214.1 U8.D9(SD_EXT1_REFCLKN)
N18794747: C77.1 U8.A15(SD5_TXDP)
N18794748: C75.1 U8.A14(SD5_TXDN)
N18846440: FB32.2 R131.1
N18846619: FB31.2 R132.1
N19008801: C79.2 U8.A17(SD4_TXDN)
N19008821: C80.2 U8.A18(SD4_TXDP)
N19160317: D14.A R65.2
N19502108: D1.K R9.2
N19502118: J5.3 R23.2 R24.1
N19504314: D1.A R8.1
N19515966: C31.1 C271.1 C272.1 C276.1 FB8.2 FB9.2 U8.AA3(VCCIO2) U8.U4(VCCIO2)
N19546170: J10.7(RATE_SELECT0) R146.2 R147.1
N19546172: J10.9(RATE_SELECT1) R148.2 R168.1
N19546420: C103.1 C118.1 C120.1 FB44.1 J10.15(VCCR)
N19546446: C106.1 C112.1 FB40.1 J10.16(VCCT)
N19650670: R271.1 U8.AD25(PB40A/PCLKT5_2)
N19650676: R272.1 U8.AE25(PB40B/PCLKC5_2)
N19699615: R270.1 U8.K18(PL15A)
N19700630: C281.1 C291.1 R233.1 U8.AF2(ADC_DP0)
N19700655: C281.2 C291.2 R234.1 U8.AE2(ADC_DN0)
N19700680: C282.1 C292.1 R235.1 U8.AE1(ADC_DP1)
N19700691: C282.2 C292.2 R236.1 U8.AD1(ADC_DN1)
N19700696: P2.1 U8.AC1(ADC_REFP0)
N19700708: P2.2 U8.AC2(ADC_REFP1)
N19700781: P1.1 R233.2
N19702062: P1.3 R235.2
N19702065: P1.4 R236.2
N19702075: P1.2 R234.2
N19821813: D9.K Q12.3(C)
N19821846: Q12.1(B) R262.2 R264.1
N19821876: D10.K Q14.3(C)
N19821909: Q14.1(B) R266.2 R268.1
N19823814: D7.K Q8.3(C)
N19823816: D8.K Q10.3(C)
N19823870: Q8.1(B) R253.2 R256.1
N19823878: Q10.1(B) R258.2 R260.1
N19825085: R203.1 U8.H21(PL3B/ULC_GPLL0C_IN)
N19825186: R201.1 U8.N23(PL31A/PCLKT7_0)
N19827755: R196.1 U8.M26(PL28A/PCLKT7_2)
N19828237: R197.1 U8.N25(PL29A/PCLKT7_1)
N19910327: R189.1 U8.L26(PL20B)
N19910328: R193.1 U8.K25(PL19B)
N19910329: R191.1 U8.L24(PL22B)
N19910330: R188.1 U8.L25(PL22A)
N19910331: R190.1 U8.K26(PL20A)
N19910908: R7.1 U3.61(EEDATA)
N19910910: R5.1 U3.63(EECS)
N19911489: R6.1 U3.62(EECLK)
N19911772: D11.1(A1) R38.1 R52.2 SW1.2
N19925030: R198.1 U8.K24(PL19A)
N19926713: B7_1.1 U8.N19(PL35A)
N19926722: B7_2.1 U8.P18(PL35B)
N20208321: C306.1 U5.6(SS)
N20210612: D8.A R27.2
N20210613: D10.A R29.2
N20210614: D7.A R26.2
N20210615: D9.A R28.2
N20271235: D36.A R137.2
N20315098: Q15.1(B) R270.2
N20351294: J55.1 Q15.3(C)

Not connected (* = marked no-connect by the designer): CN1 A5(TCK)* A6(TDI)* A7(TDO)* A8(TMS)* A19(A19_RSVD)* A32(A32_RSVD)* B5(SMCLK)* B6(SMDAT)* B9(TRST#)* B10(B10_3V3AUX)* B11(WAKE#)* B12(RSVD)* B30(B30_RSVD)*; J9 4 5; J10 MH1 MH2; J12 MH1 MH2; J16 MH1 MH2; J17 MH1 MH2; J19 6*; SW2 4(P1) 5(P3); U2 7(NC); U3 21(ADBUS4)* 22(ADBUS5)* 23(ADBUS6)* 26(ACBUS0)* 27(ACBUS1)* 28(ACBUS2)* 29(ACBUS3)* 30(ACBUS4)* 32(ACBUS5)* 33(ACBUS6)* 34(ACBUS7)* 41(BDBUS3)* 43(BDBUS4)* 44(BDBUS5)* 45(BDBUS6)* 46(BDBUS7)* 48(BCBUS0)* 52(BCBUS1)* 53(BCBUS2)* 54(BCBUS3)* 55(BCBUS4)* 57(BCBUS5)* 58(BCBUS6)*; U4 2(DNC)* 3(DNC_1)* 15(DNC_2)* 16(DNC_3)* 26(DNC_4)* 28(INH/UVLO)*; U8 A2(NC)* A3(NC)* A5(NC)* A6(NC)* AA1(PR65A) AA4(PR62B) AA8(NC)* AA9(NC)* AA15(NC)* AA16(NC)* AA19(NC)* AA20(NC)* AA24(PB28B) AA25(NC)* AA26(NC)* AB1(PR65B) AB2(PR67B)* AB3(PR67A)* AB16(NC)* AB20(PB48B/VREF5_2)* AB23(PB32A) AB24(PB32B) AB25(PB34A) AB26(PB30B) AC16(NC)* AC20(PB48A)* AC24(PB34B) AC25(PB36A) AC26(PB30A) AD7(NC)* AD8(NC)* AD16(NC)* AD17(NC)* AD23(PB38B) AD26(PB36B) AE7(NC)* AE8(NC)* AE16(NC)* AE17(NC)* AE18(NC)* AF7(NC)* AF8(NC)* AF17(NC)* AF18(NC)* B1(NC)* B4(NC)* B7(NC)* C1(NC)* C4(NC)* C6(NC)* C8(NC)* D2(NC)* D3(NC)* D5(NC)* E1(NC)* E4(NC)* E6(NC)* E7(NC)* E8(NC)* E9(NC)* F1(NC)* F3(NC)* F9(NC)* F11(NC)* G8(NC)* G9(NC)* G11(NC)* H8(NC)* H9(NC)* H10(NC)* H11(NC)* H12(NC)* H23(PL4B) H26(PL6A) J8(NC)* J9(NC)* J10(NC)* K9(NC)* K10(NC)* K11(NC)* K12(NC)* L18(NC)* L20(PL26A)* L23(PL24A)* M18(NC)* M19(NC)* M22(NC)* M23(NC)* M24(NC)* M25(NC)* N18(NC)* N24(PL29B)* N26(PL28B)* P1(NC)* P2(NC)* P3(NC)* P6(NC)* P7(NC)* P19(PL38A)* P20(PL38B)* R1(NC)* R2(NC)* R3(NC)* T1(PR42A/PCLKT2_0) T2(PR40B) T3(PR40A) U1(PR42B) U2(PR44A/PCLKT2_1) U3(PR44B) W8(NC)* W9(NC)* W19(NC)* W20(NC)* W22(PB12A)* W25(PB8A/ADC_CP3)* W26(PB8B/ADC_CN3)* Y2(PR64B) Y4(PR62A) Y8(NC)* Y9(NC)* Y15(NC)* Y19(NC)* Y20(NC)* Y21(NC)* Y22(NC)* Y25(NC)* Y26(NC)*; U14 2(NC); U15 2(NC)*

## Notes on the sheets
sheet 13
- BANK 5
  1.8V
- DIP SWITCH
- 125Mhz for 1G Ports
- Switch Signal Map
- U12 PIN
- SIGNAL
- SWITCH
- AA23
- SWITCH1
- 1
- AB22
- SWITCH2
- 2
- AC22
- SWITCH3
- 3
- AA22
- SWITCH4
- 4
- W21
- SWITCH5
- 5
- 1G SFP
- 1G SFP
sheet 14
- BANK 2
- 3.3V/1.8V
sheet 15
- ADC
- 4 PinMatting-Part
- Contact Termination Part
- Contact Termination Part
- Contact Termination Part
- Contact Termination Part
- 2 Pin Matting-Part
- Contact Termination Part
- Contact Termination Part
- DIGITAL GND
- SERDES GND
sheet 16
- FTDI High-Speed USB
- Configuration of FPGA Via FTDI
- Connect 1-2 For UART
  Connect 3-2 For I2C
- USB2.0 CONNECTOR
- USB ESD Protection
- FTDI Reset
- Shall We
  connect
  1M and
  0.1uF/500V
sheet 17
- SERDES QUADS, PCIe EDGE Connector
- SerDes Aux Decaps
- PLACE 100R close to the FPGA
- OSC 161.1328Mhz
- X4 PCIe Board Fingers
  B side = Primary Component Side(TOP)
  A side = Secondary Component
  Side(BOTTOM)
  All Nets are 85-ohm differential
  pairs.
  The P and N traces shall be <5mil
  matched in length
- Default Short 2-4 for PCIe X4
- A side Solder side and B side is component
- Short 1-2 for PCIe X1
sheet 18
- SerDes PLL Decaps
- 10G SFP CONNECTOR
- 10G SFP CONNECTOR
- Decaps for  SD PWR Lines
- SERDES POWER
sheet 19
- BANK 7
- 3.3V
sheet 20
- Power Regulators
- 12V INPUT
- 12V-5V
- 5V-1V
  FOR FPGA
- Added Ferrite bead
- 5.83K is Actual
- Decaps VCC_Core_VCC_Aux and Vcc_AuxA
- FPGA POWER
